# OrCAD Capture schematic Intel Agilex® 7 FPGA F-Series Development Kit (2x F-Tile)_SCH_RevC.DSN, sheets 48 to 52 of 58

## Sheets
48 PG52 VCCH_SDM: size C
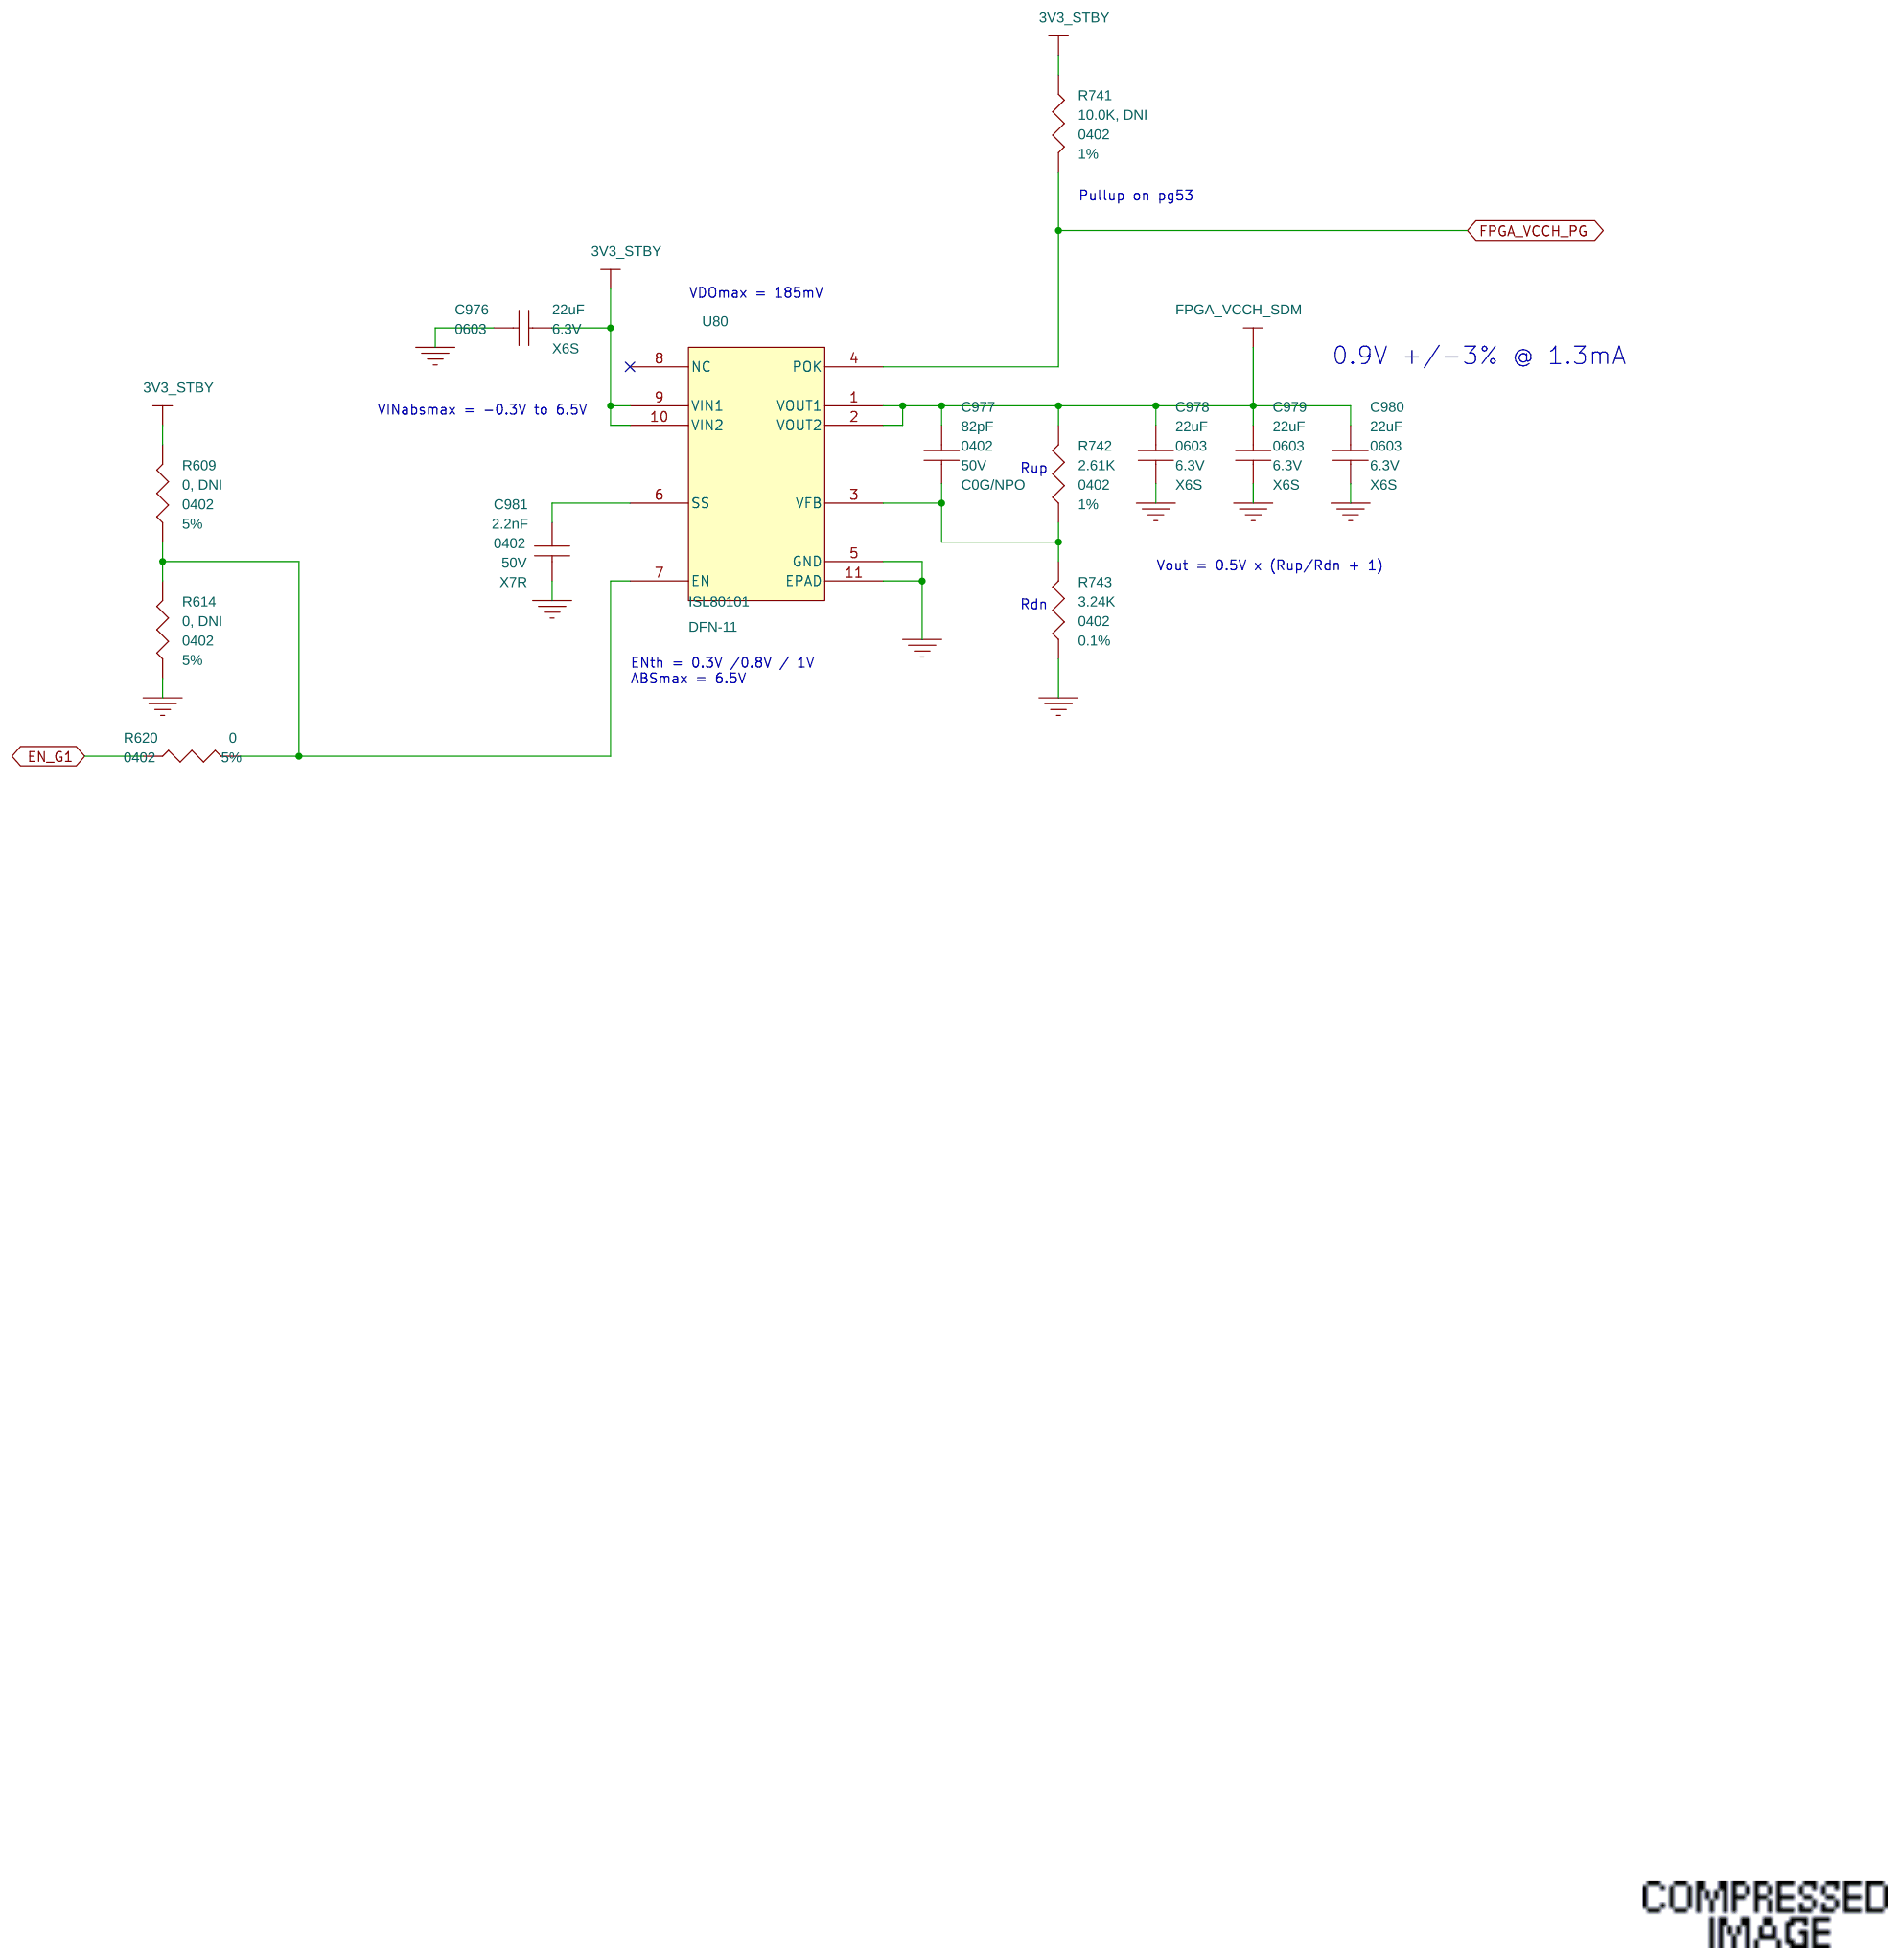
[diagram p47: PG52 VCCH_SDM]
49 PG53 VCCERT_FGT_GXF, VCCR_CORE: size C
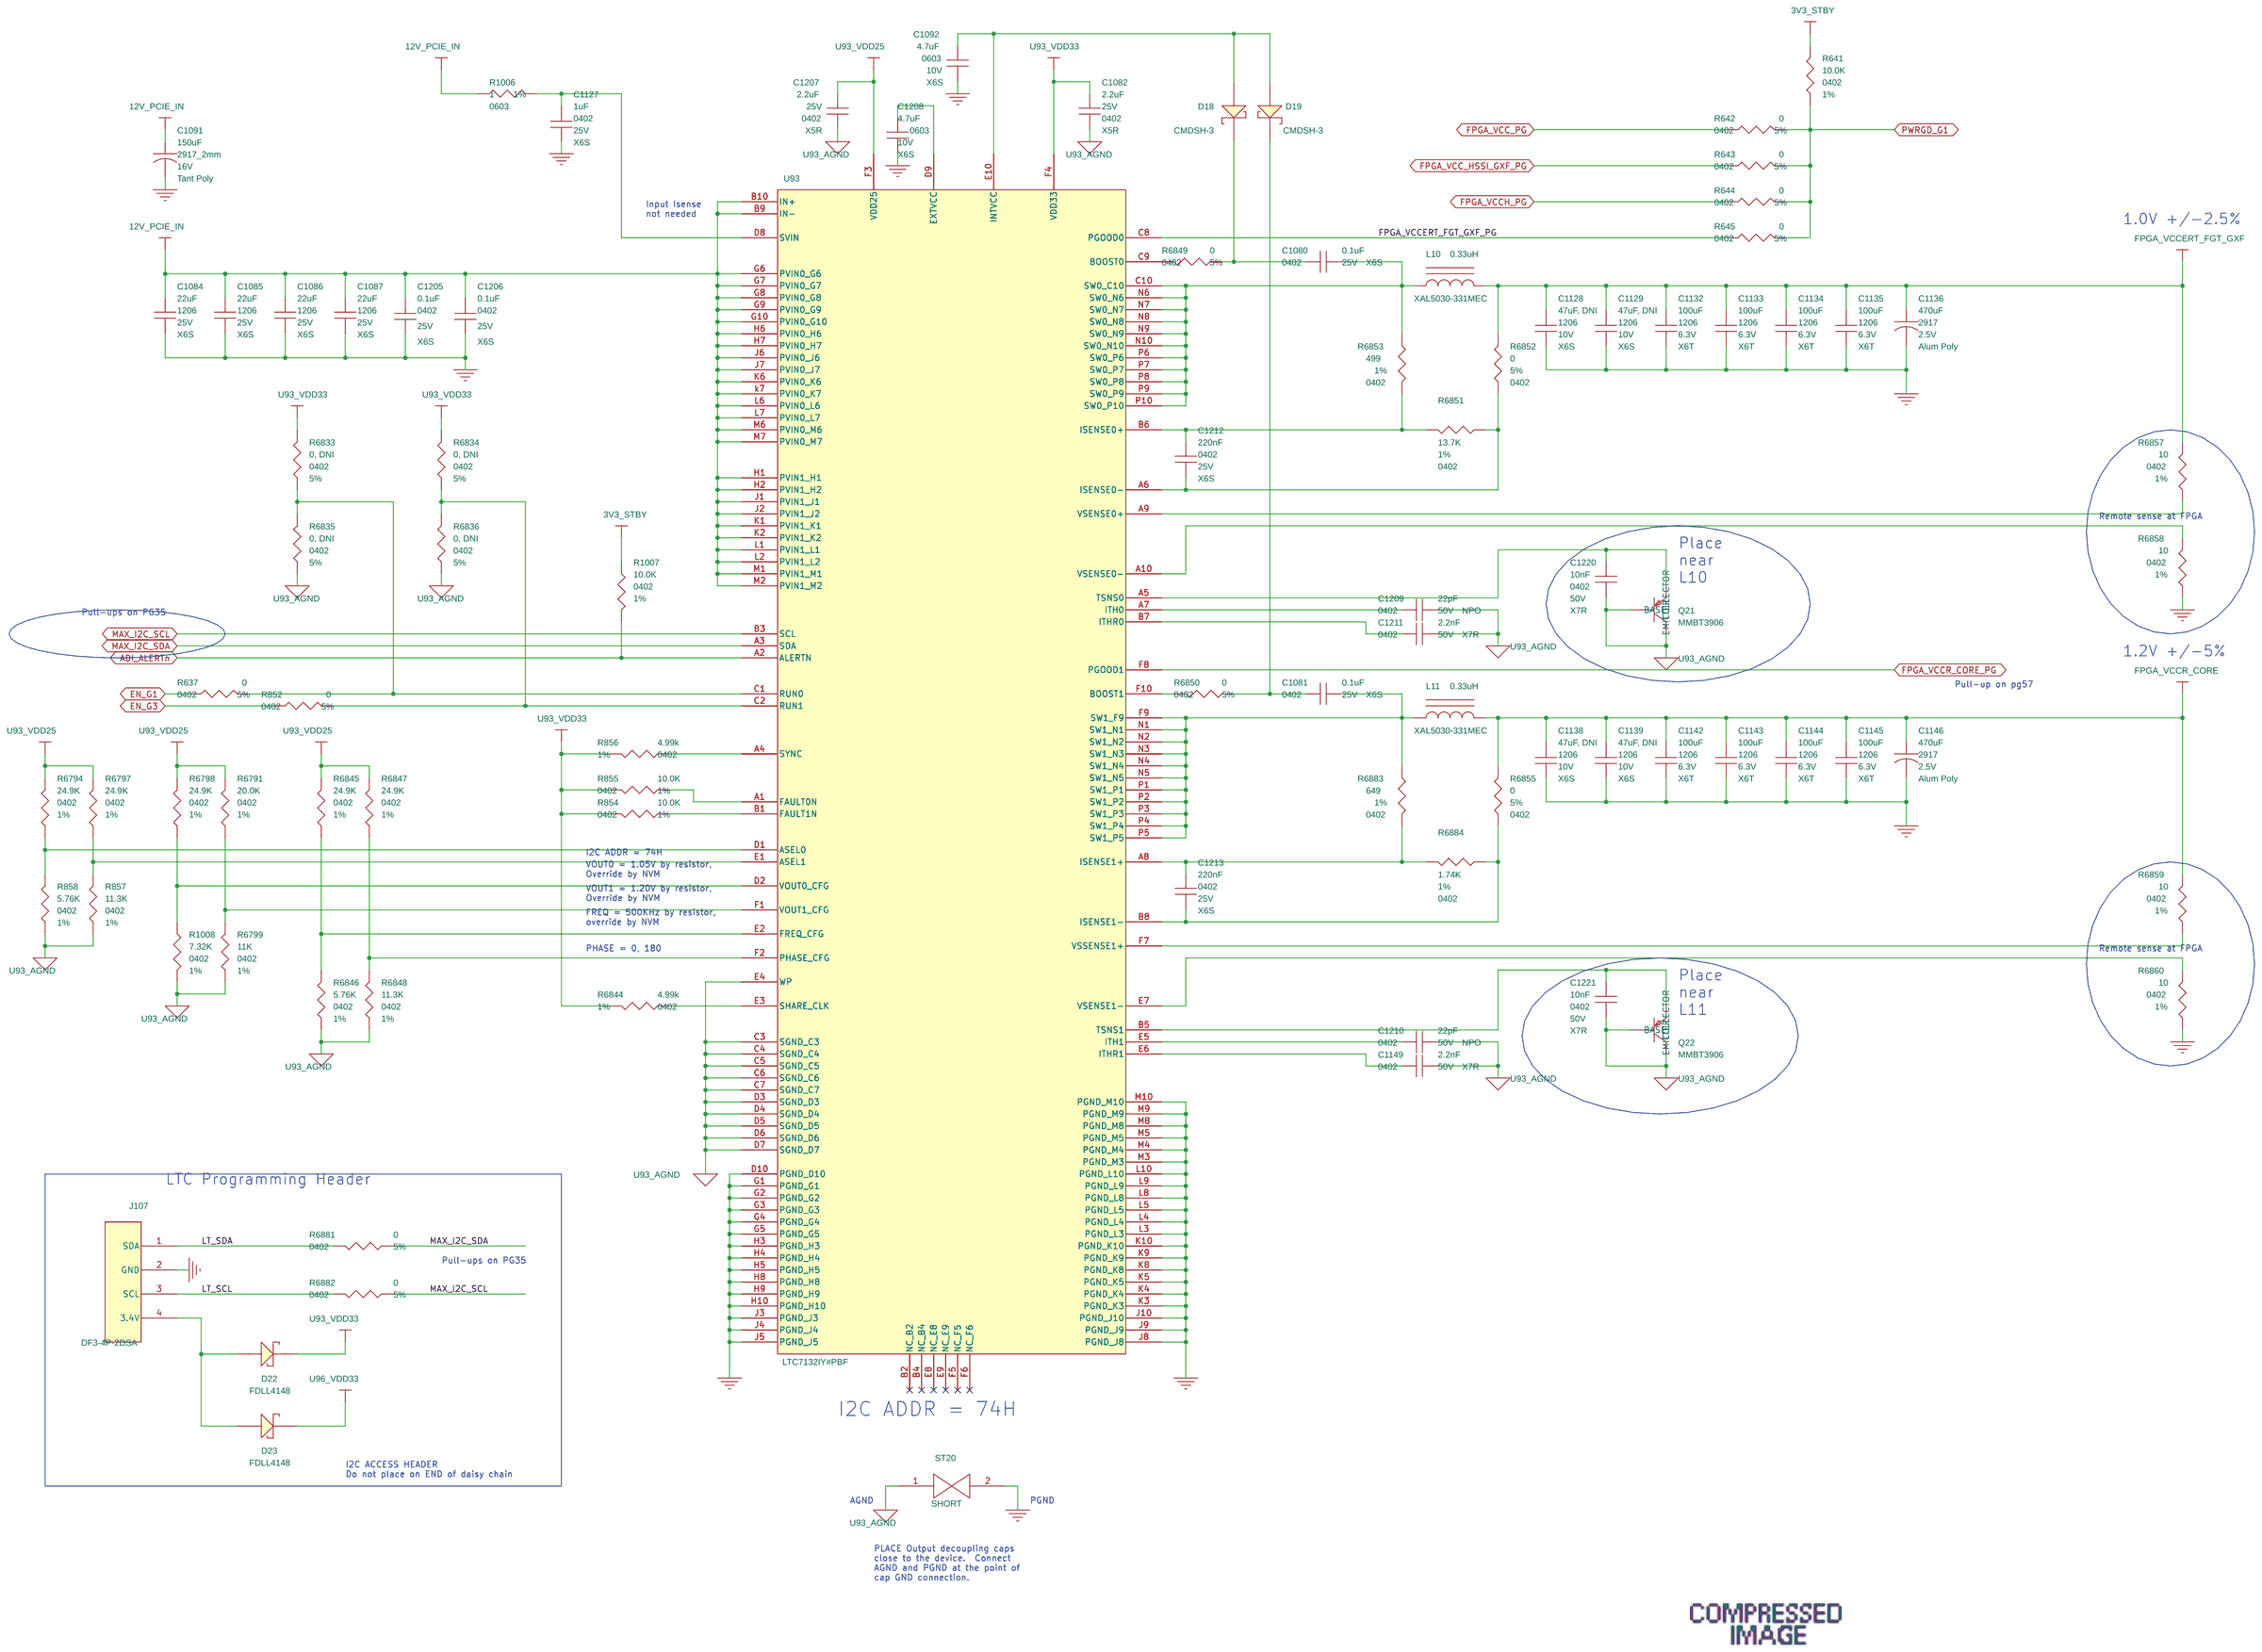
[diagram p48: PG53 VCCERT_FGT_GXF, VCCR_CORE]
50 PG54 VCCPT, VCCIO_1V2: size C
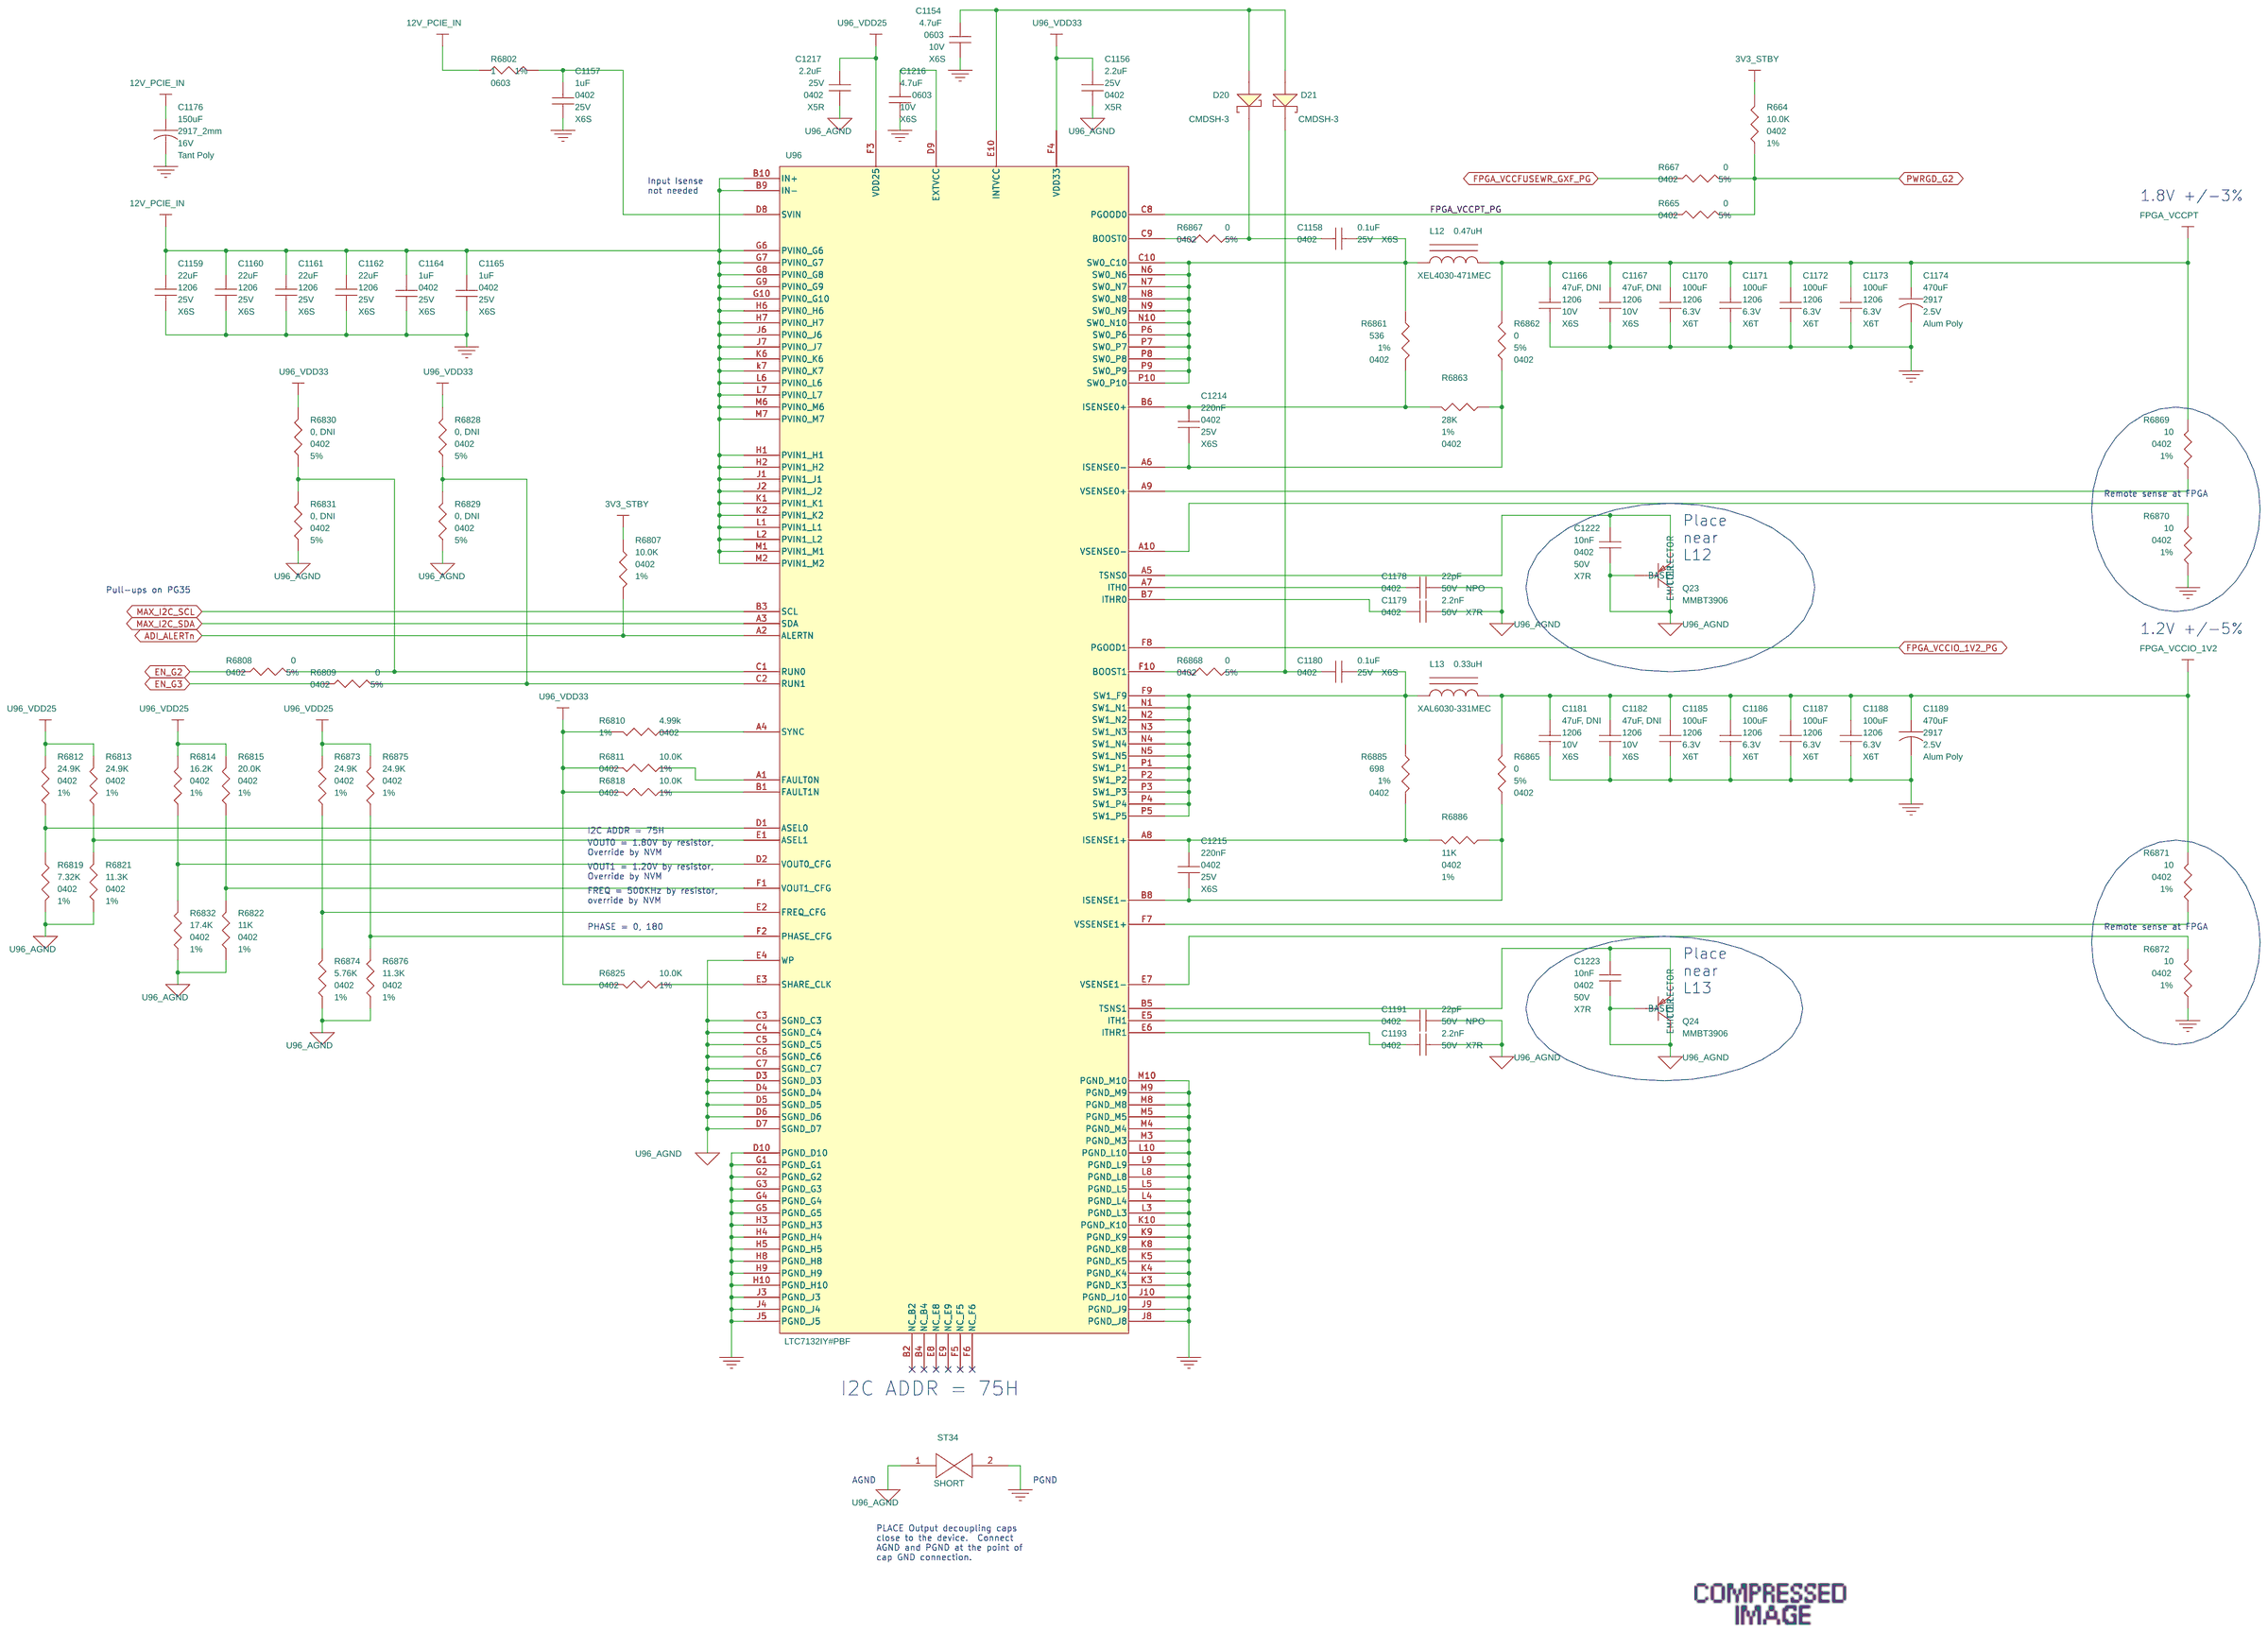
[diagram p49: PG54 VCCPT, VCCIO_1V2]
51 PG55 VCCFUSEWR_GXF: size C
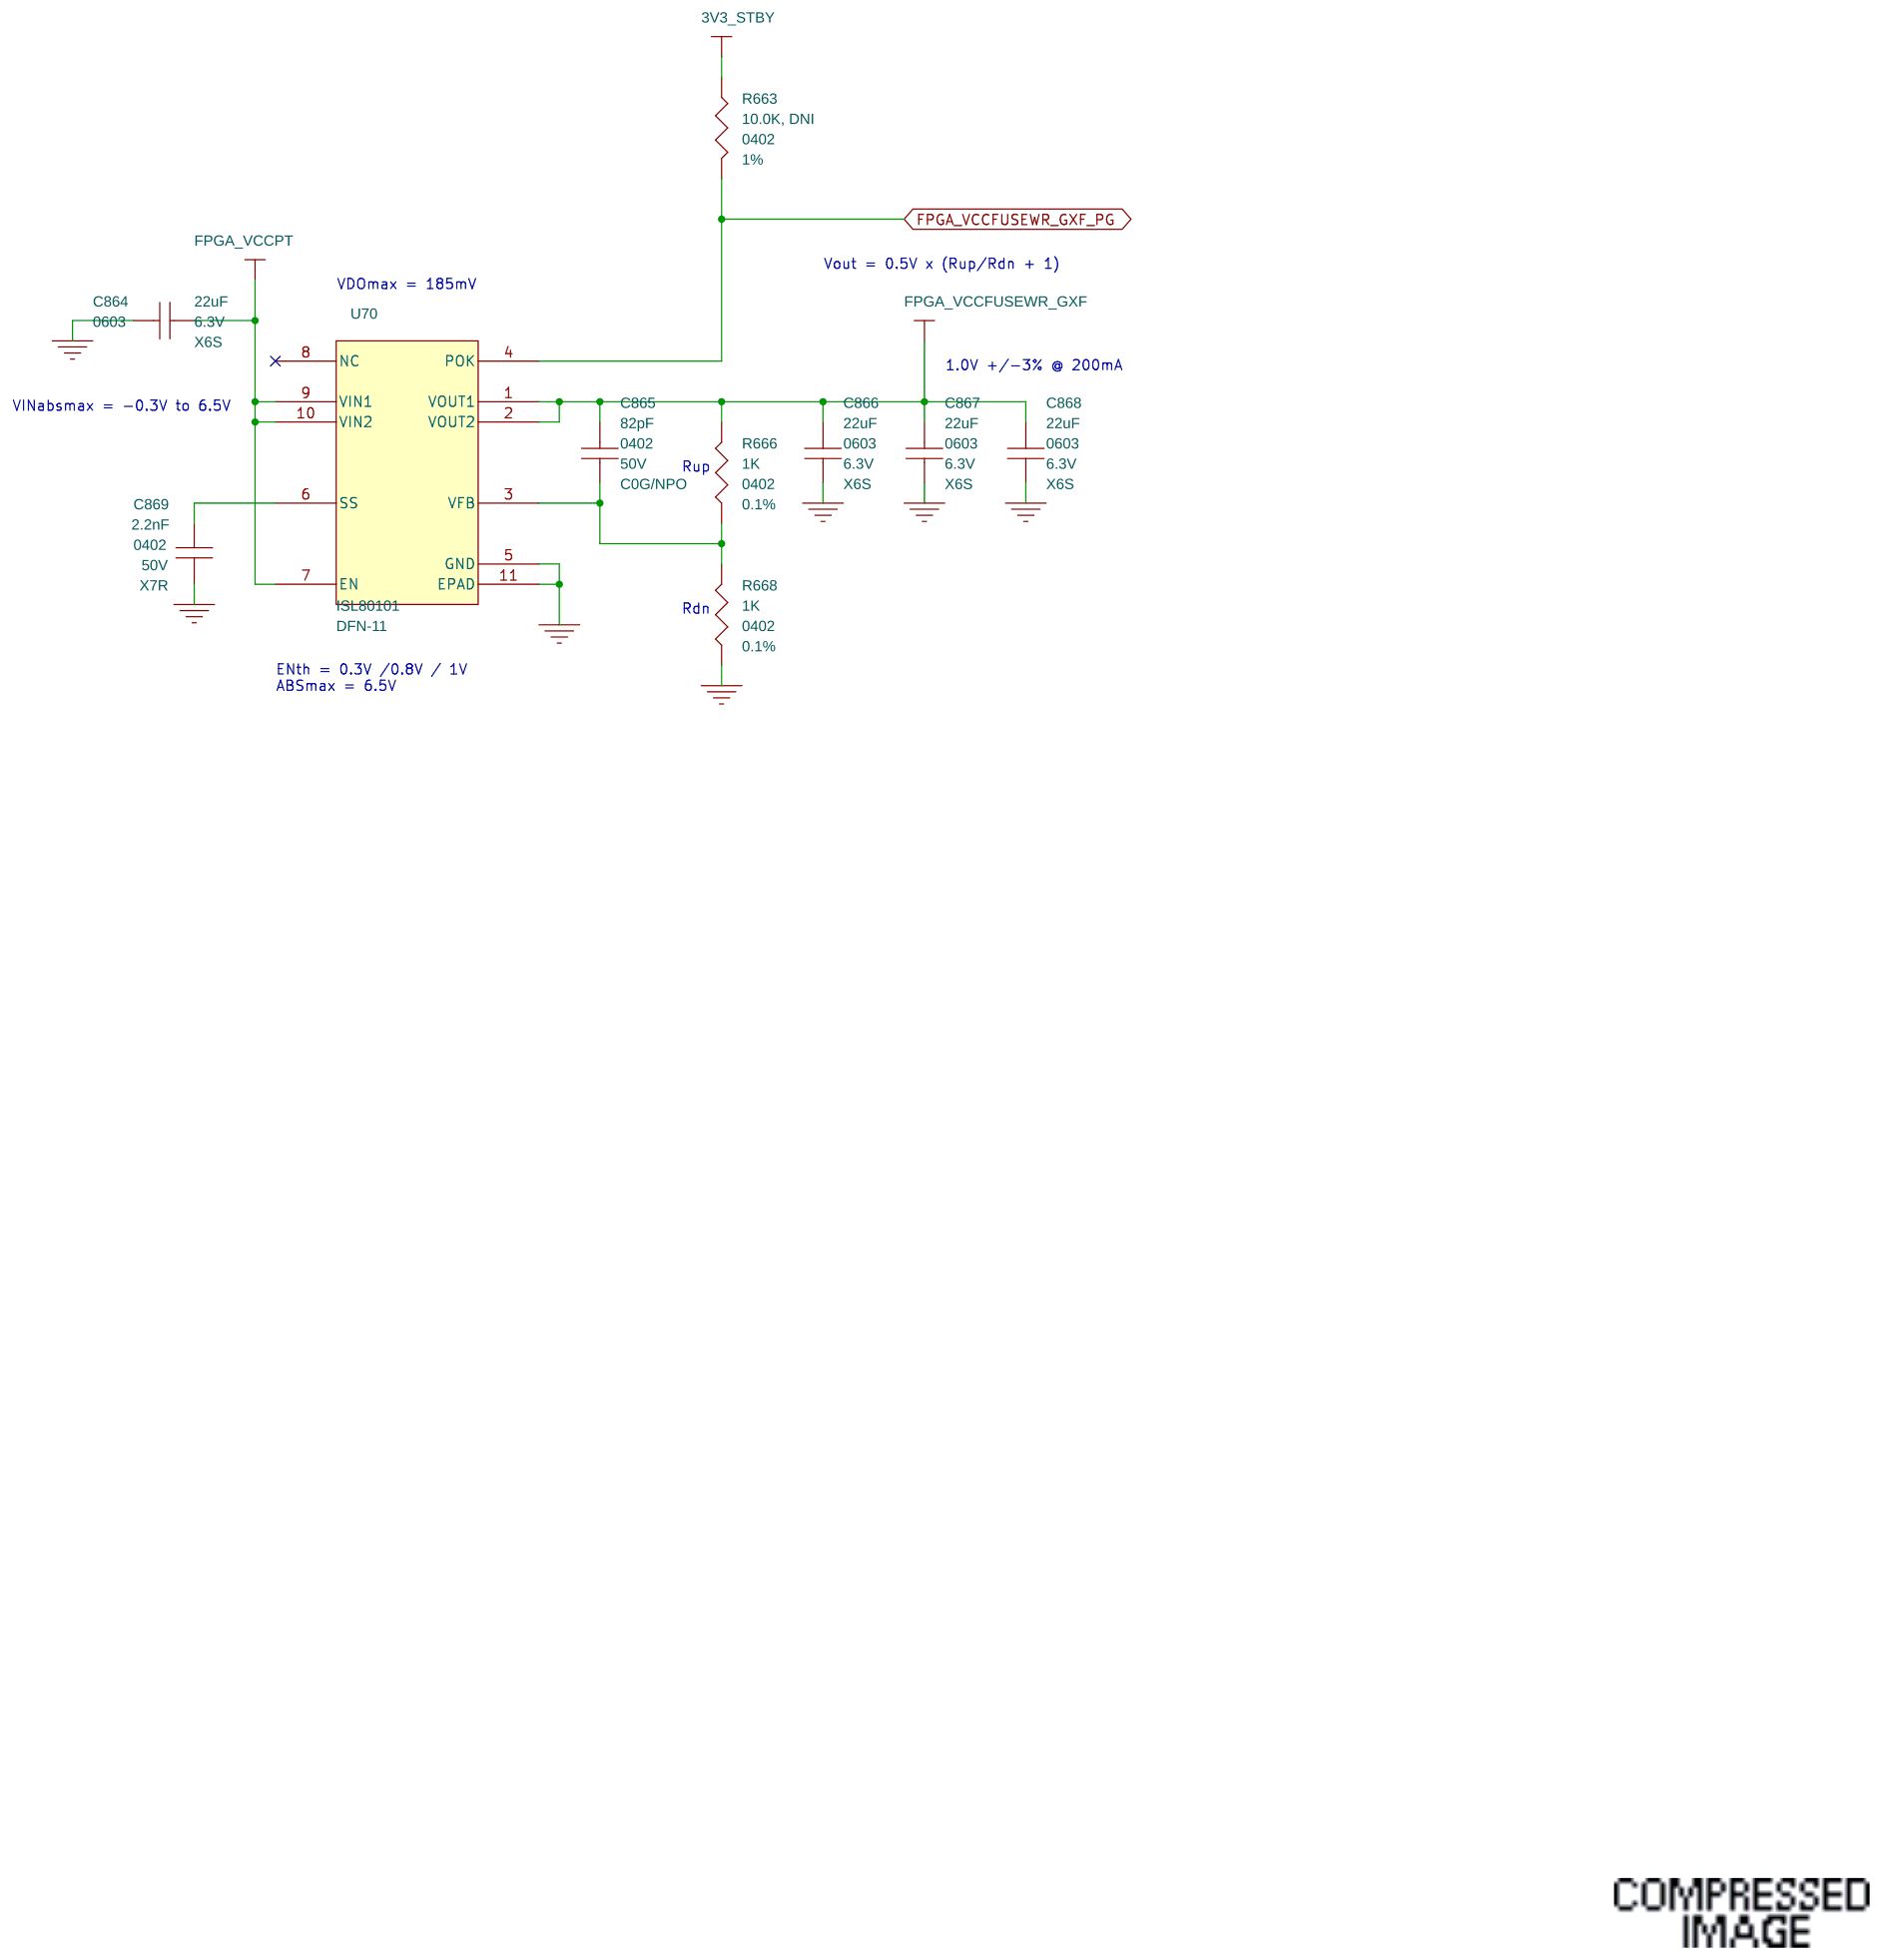
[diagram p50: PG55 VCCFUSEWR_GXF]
52 PG56 VCCBAT BATTERY: size C
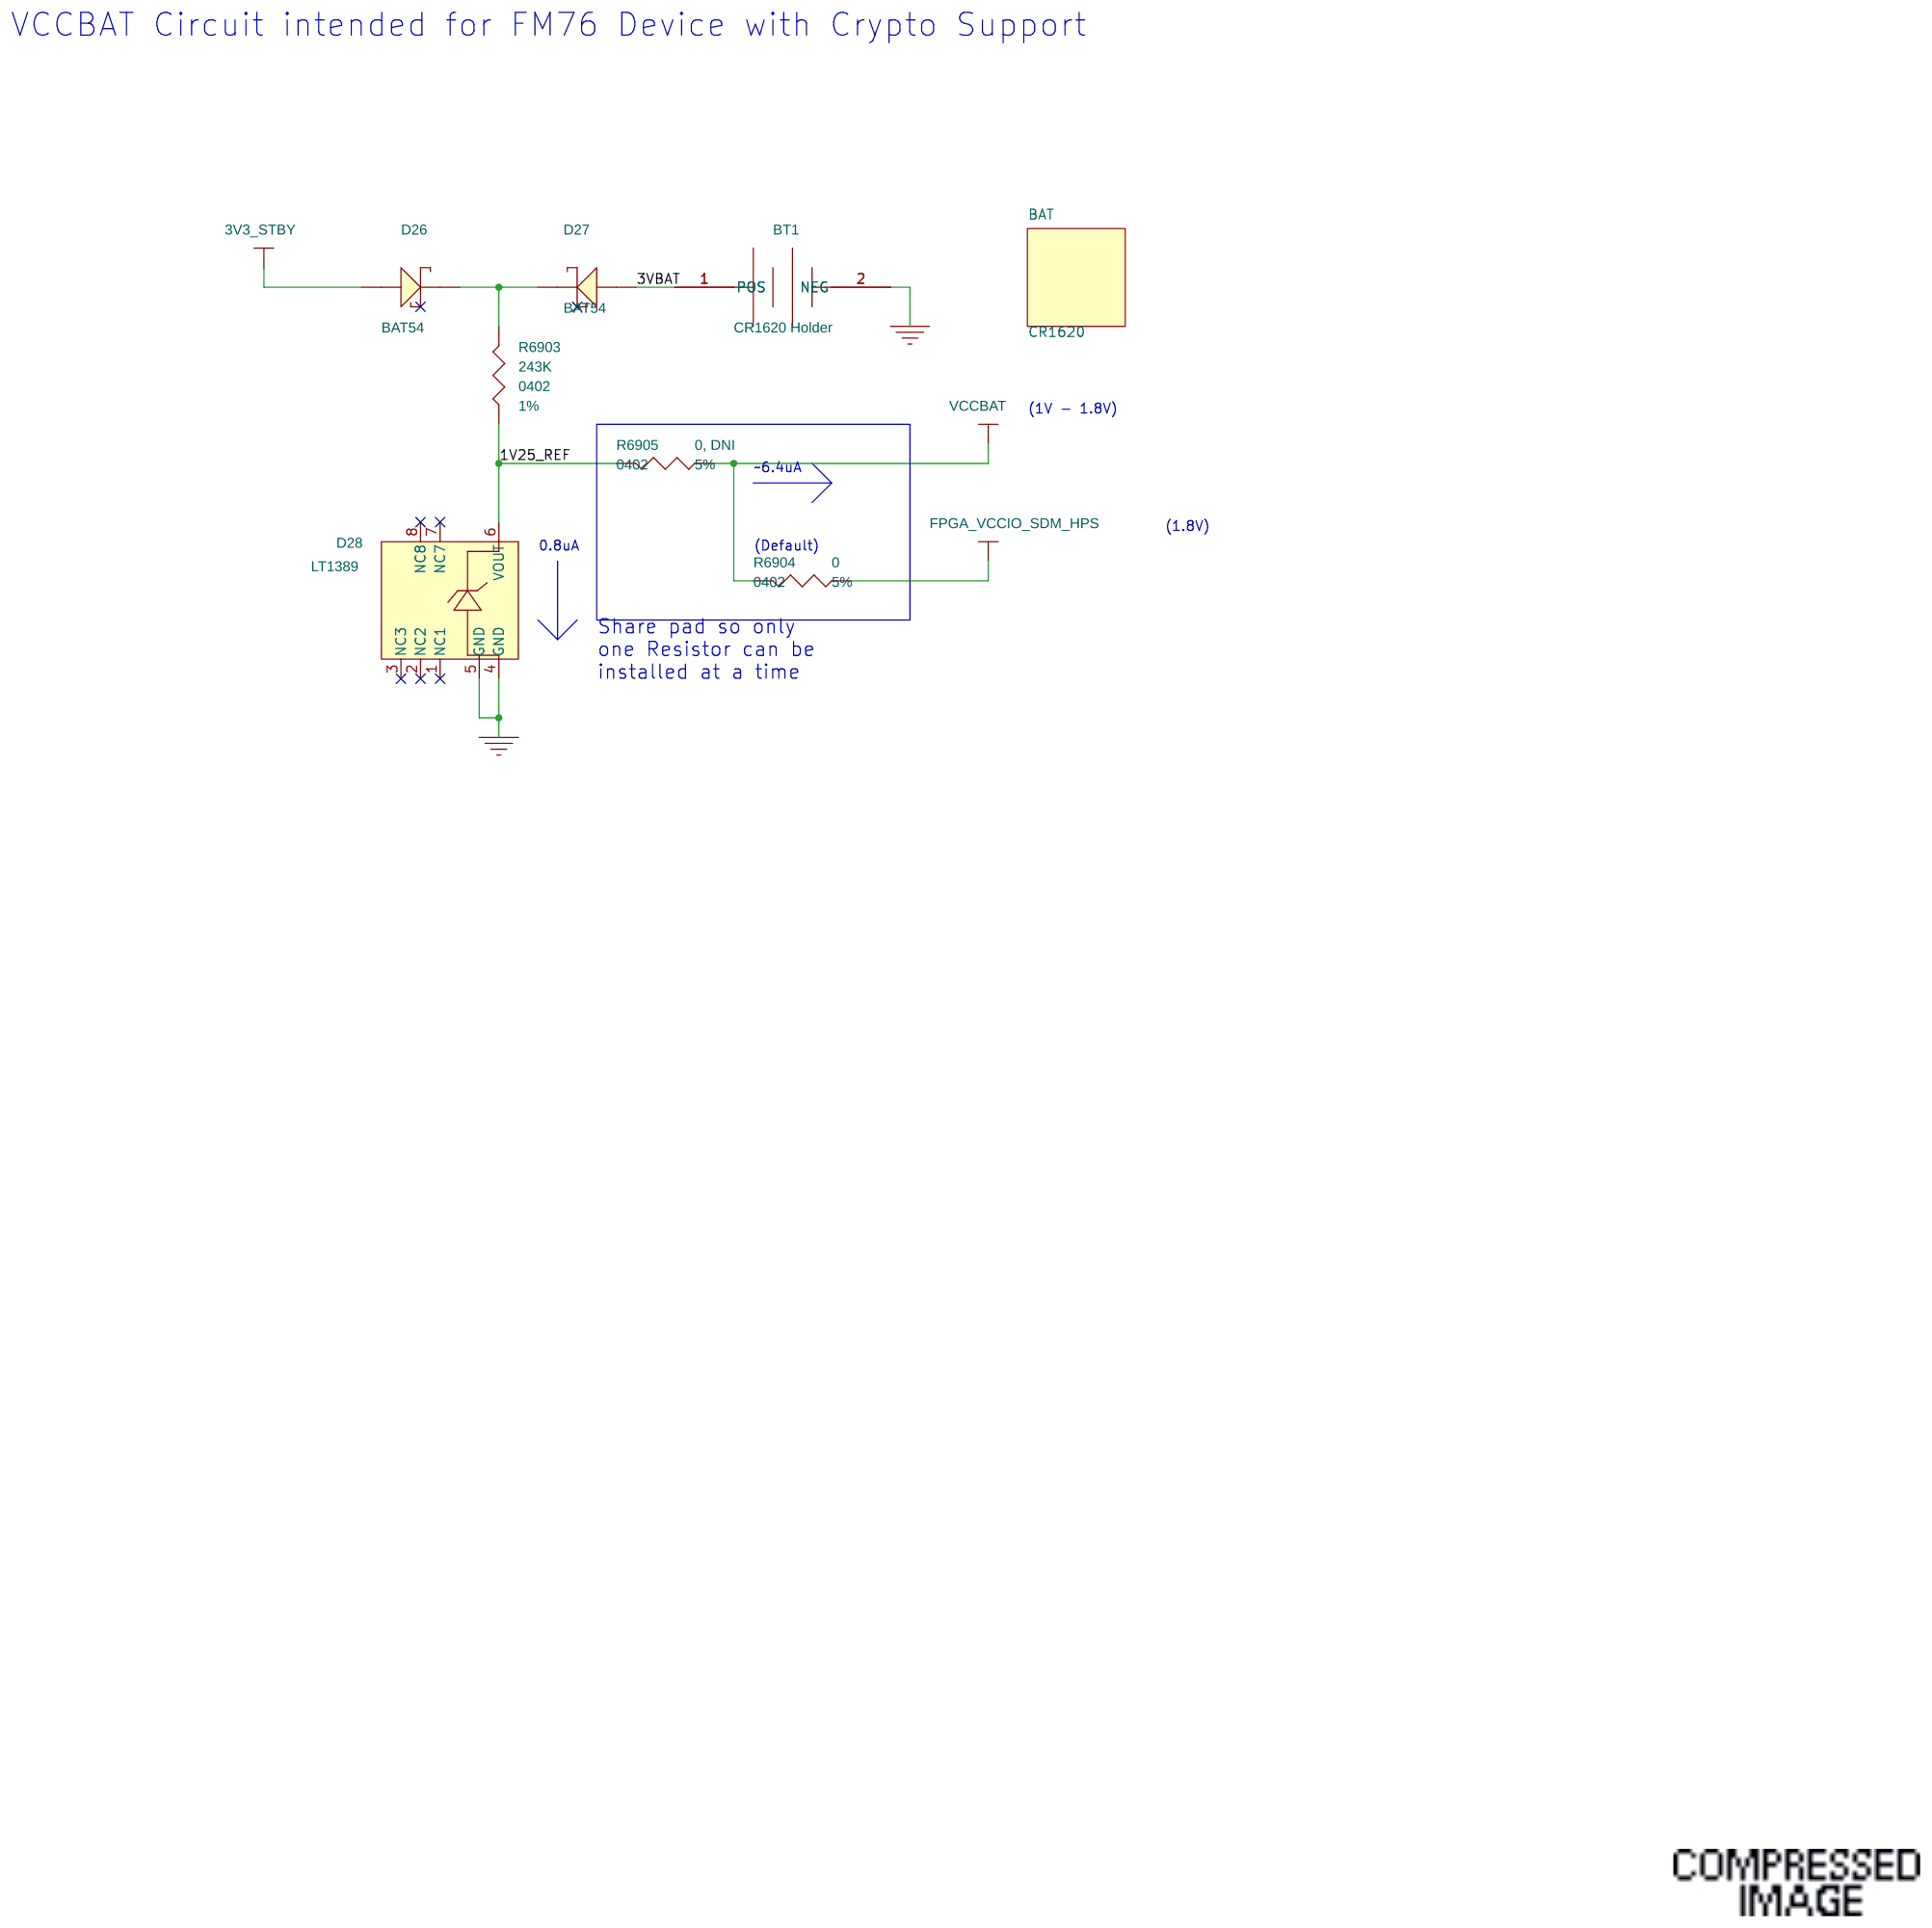
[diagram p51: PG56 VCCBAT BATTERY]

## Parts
sheet PG52 VCCH_SDM
C976  22uF  [0603]
C977  82pF  [0402]
C978  22uF  [0603]
C979  22uF  [0603]
C980  22uF  [0603]
C981  2.2nF  [0402]
R609  0, DNI  [0402]
R614  0, DNI  [0402]
R620  0  [0402]
R741  10.0K, DNI  [0402]
R742  2.61K  [0402]
R743  3.24K  [0402]
U80  ISL80101  [DFN-11]
sheet PG53 VCCERT_FGT_GXF, VCCR_CORE
C1080  0.1uF  [0402]
C1081  0.1uF  [0402]
C1082  2.2uF  [0402]
C1084  22uF  [1206]
C1085  22uF  [1206]
C1086  22uF  [1206]
C1087  22uF  [1206]
C1091  150uF  [2917_2mm]
C1092  4.7uF  [0603]
C1127  1uF  [0402]
C1128  47uF, DNI  [1206]
C1129  47uF, DNI  [1206]
C1132  100uF  [1206]
C1133  100uF  [1206]
C1134  100uF  [1206]
C1135  100uF  [1206]
C1136  470uF  [2917]
C1138  47uF, DNI  [1206]
C1139  47uF, DNI  [1206]
C1142  100uF  [1206]
C1143  100uF  [1206]
C1144  100uF  [1206]
C1145  100uF  [1206]
C1146  470uF  [2917]
C1149  2.2nF  [0402]
C1205  0.1uF  [0402]
C1206  0.1uF  [0402]
C1207  2.2uF  [0402]
C1208  4.7uF  [0603]
C1209  22pF  [0402]
C1210  22pF  [0402]
C1211  2.2nF  [0402]
C1212  220nF  [0402]
C1213  220nF  [0402]
C1220  10nF  [0402]
C1221  10nF  [0402]
D18  CMDSH-3  [SOD323]
D19  CMDSH-3  [SOD323]
D22  FDLL4148  [SOD-80]
D23  FDLL4148  [SOD-80]
J107  DF3-4P-2DSA  [DF3-4P-2DSA_01]
L10  0.33uH  [XAL5030]
L11  0.33uH  [XAL5030]
Q21  MMBT3906  [SC75_SOT416]
Q22  MMBT3906  [SC75_SOT416]
R637  0  [0402]
R641  10.0K  [0402]
R642  0  [0402]
R643  0  [0402]
R644  0  [0402]
R645  0  [0402]
R852  0  [0402]
R854  10.0K  [0402]
R855  10.0K  [0402]
R856  4.99k  [0402]
R857  11.3K  [0402]
R858  5.76K  [0402]
R1006  1  [0603]
R1007  10.0K  [0402]
R1008  7.32K  [0402]
R6791  20.0K  [0402]
R6794  24.9K  [0402]
R6797  24.9K  [0402]
R6798  24.9K  [0402]
R6799  11K  [0402]
R6833  0, DNI  [0402]
R6834  0, DNI  [0402]
R6835  0, DNI  [0402]
R6836  0, DNI  [0402]
R6844  4.99k  [0402]
R6845  24.9K  [0402]
R6846  5.76K  [0402]
R6847  24.9K  [0402]
R6848  11.3K  [0402]
R6849  0  [0402]
R6850  0  [0402]
R6851  13.7K  [0402]
R6852  0  [0402]
R6853  499  [0402]
R6855  0  [0402]
R6857  10  [0402]
R6858  10  [0402]
R6859  10  [0402]
R6860  10  [0402]
R6881  0  [0402]
R6882  0  [0402]
R6883  649  [0402]
R6884  1.74K  [0402]
ST20  SHORT  [SHORT]
U93  LTC7132IY#PBF  [BGA-140]
sheet PG54 VCCPT, VCCIO_1V2
C1154  4.7uF  [0603]
C1156  2.2uF  [0402]
C1157  1uF  [0402]
C1158  0.1uF  [0402]
C1159  22uF  [1206]
C1160  22uF  [1206]
C1161  22uF  [1206]
C1162  22uF  [1206]
C1164  1uF  [0402]
C1165  1uF  [0402]
C1166  47uF, DNI  [1206]
C1167  47uF, DNI  [1206]
C1170  100uF  [1206]
C1171  100uF  [1206]
C1172  100uF  [1206]
C1173  100uF  [1206]
C1174  470uF  [2917]
C1176  150uF  [2917_2mm]
C1178  22pF  [0402]
C1179  2.2nF  [0402]
C1180  0.1uF  [0402]
C1181  47uF, DNI  [1206]
C1182  47uF, DNI  [1206]
C1185  100uF  [1206]
C1186  100uF  [1206]
C1187  100uF  [1206]
C1188  100uF  [1206]
C1189  470uF  [2917]
C1191  22pF  [0402]
C1193  2.2nF  [0402]
C1214  220nF  [0402]
C1215  220nF  [0402]
C1216  4.7uF  [0603]
C1217  2.2uF  [0402]
C1222  10nF  [0402]
C1223  10nF  [0402]
D20  CMDSH-3  [SOD323]
D21  CMDSH-3  [SOD323]
L12  0.47uH  [XEL4030]
L13  0.33uH  [XAL6030]
Q23  MMBT3906  [SC75_SOT416]
Q24  MMBT3906  [SC75_SOT416]
R664  10.0K  [0402]
R665  0  [0402]
R667  0  [0402]
R6802  1  [0603]
R6807  10.0K  [0402]
R6808  0  [0402]
R6809  0  [0402]
R6810  4.99k  [0402]
R6811  10.0K  [0402]
R6812  24.9K  [0402]
R6813  24.9K  [0402]
R6814  16.2K  [0402]
R6815  20.0K  [0402]
R6818  10.0K  [0402]
R6819  7.32K  [0402]
R6821  11.3K  [0402]
R6822  11K  [0402]
R6825  10.0K  [0402]
R6828  0, DNI  [0402]
R6829  0, DNI  [0402]
R6830  0, DNI  [0402]
R6831  0, DNI  [0402]
R6832  17.4K  [0402]
R6861  536  [0402]
R6862  0  [0402]
R6863  28K  [0402]
R6865  0  [0402]
R6867  0  [0402]
R6868  0  [0402]
R6869  10  [0402]
R6870  10  [0402]
R6871  10  [0402]
R6872  10  [0402]
R6873  24.9K  [0402]
R6874  5.76K  [0402]
R6875  24.9K  [0402]
R6876  11.3K  [0402]
R6885  698  [0402]
R6886  11K  [0402]
ST34  SHORT  [SHORT]
U96  LTC7132IY#PBF  [BGA-140]
sheet PG55 VCCFUSEWR_GXF
C864  22uF  [0603]
C865  82pF  [0402]
C866  22uF  [0603]
C867  22uF  [0603]
C868  22uF  [0603]
C869  2.2nF  [0402]
R663  10.0K, DNI  [0402]
R666  1K  [0402]
R668  1K  [0402]
U70  ISL80101  [DFN-11]
sheet PG56 VCCBAT BATTERY
BAT  CR1620
BT1  CR1620 Holder  [16mm_Bat_Holder]
D26  BAT54  [SOT-23-3]
D27  BAT54  [SOT-23-3]
D28  LT1389  [S8]
R6903  243K  [0402]
R6904  0  [0402]
R6905  0, DNI  [0402]

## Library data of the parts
C864 C866-C868 C976 C978-C980 = CAP: CAP CER 22UF 6.3V X6S 0603; AGILE_LINK: http://sj-agile9app/Agile/PLMServlet?action=OpenEmailObject&classid=10000&objid=257560276; Item Num: H63299-001; LIFECYCLE_PHASE: Active; Lead Free Status: Not Lead Free; MFR_LIFECYCLE: Active; Manufacturer: Murata; Manufacturer Part Num: GRM188C80J226ME15D; Num Pins: 2; PART_SUBCLASS: CAPACITORS; RATED_VOLTAGE: 6.3V; RoHS Compliant: RoHS Compliant; TOLERANCE: 20%; Temperature Coefficient: X6S
C865 C977 = CAP: CAP CER 82PF 50V C0G/NPO 0402; Dielectric: C0G/NPO; Item Num: K13615-001; Lead Free Status: Yes; Manufacturer: Yageo; Manufacturer Part Num: CC0402JRNPO9BN820; Num Pins: 2; Part Class: CAPACITORS; RoHS Compliant: Yes; Temperature Coefficient: C0G/NPO; Tolerance: 5%; Voltage Rating: 50V
C869 C981 = CAP: CAP CER 2200PF 50V 10% X7R 0402; CAPACITANCE: 2200pF; Dielectric: X7R; Item Num: K13631-001; LIFECYCLE_PHASE: Active; Lead Free Status: Lead Free; Manufacturer: TDK; Manufacturer Part Num: CGJ2B2X7R1E222K050BA; Num Pins: 2; PART_SUBCLASS: CAPACITORS; Part Class: CAPACITORS; RATED_VOLTAGE: 50V; RoHS Compliant: RoHS Compliant; Temperature Coefficient: X7R; Tolerance: +/-10%
R609 R614 R6828-R6831 R6833-R6836 = RESISTOR: RES ZERO OHM 1/16W 5% 0402 SMD; IPN: A93549-001; Item Num: A93549-001; Lead Free Status: Yes; Manufacturer: Yageo; Manufacturer Part Num: RC0402JR-070RL; Num Pins: 2; Part Class: RESISTORS; RoHS Compliant: Yes; Tolerance: 5%
R620 R637 R642-R645 R665 R667 R852 R6808 R6809 R6852 R6855 R6862 R6865 = RESISTOR: RES ZERO OHM 1/16W 5% 0402 SMD; Item Num: A93549-001; Lead Free Status: Yes; Manufacturer: Yageo; Manufacturer Part Num: RC0402JR-070RL; Num Pins: 2; Part Class: RESISTORS; RoHS Compliant: Yes; Tolerance: 5%
R663 R741 = RESISTOR: RES,10.0K OHMS,1.0%,1/16W, 0402; AGILE_LINK: http://sj-agile9app/Agile/PLMServlet?action=OpenEmailObject&classid=10000&objid=146548997; Item Num: K28115-001; LIFECYCLE_PHASE: Active; Lead Free Status: Yes; MFR_LIFECYCLE: Active; Manufacturer: Panasonic; Manufacturer Part Num: ERJ-2RKF1002X; Num Pins: 2; PART_SUBCLASS: RESISTORS; POWER: 1/16W; RESISTANCE: 10.0K; RoHS Compliant: Yes; TOLERANCE: 1%
R742 = RESISTOR: RES SMD 2.61K 1% 1/16W 0402; Item Num: A93548-419; Lead Free Status: Yes; Manufacturer: RC0402FR-072K61L; Manufaturer: Yageo; Num Pins: 2; Part Class: RESISTORS; RoHS Compliant: Yes; TOLERANCE: 1%
R743 = RESISTOR: RES SMD 3.24KOHM 0.1% 1/16W 0402; Item Num: C79651-108; Lead Free Status: Yes; Manufacturer: Yageo; Manufacturer Part Num: RE0402BRE073K24L; Num Pins: 2; Part Class: Resistors; Power Rating: 1/16W; RoHS Compliant: Yes; TOLERANCE: 0.1%
U70 U80 = EY1501di-adj: IC, Linear Regulator, 1A; Item Num: E81353-001; Manufacturer: Intel/Enpirion; Manufacturer Part Num: EY1501DI-ADJ
C1080 C1081 C1158 C1180 C1205 C1206 = CAP: CAP CER 0.1UF 25V X6S 0402; Dielectric: X6S; IPN: K19434-001; Item Num: K19434-001; LIFECYCLE_PHASE: Active; Lead Free Status: Lead Free; MFR_LIFECYCLE: Active; Manufacturer: Murata; Manufacturer Part Num: GRM155C81E104KA12D; Num Pins: 2; PART_SUBCLASS: CAPACITORS; Part Class: CAPACITORS; RATED_VOLTAGE: 25V; RoHS Compliant: RoHS Compliant; Temperature Coefficient: X6S; Tolerance: 10%
C1082 C1156 C1207 C1217 = CAP: CAPC,X5R,0402,2.2UF,25.00V,+/- 10%; CLASS: DISCRETE; Dielectric Type: X5R; FPLIST: CC0805N,CC0805L,CC0805M; IPN: H87713-001; Item Num: H87713-001; Manufacturer: Murata; Manufacturer PN: GRM155R61E225KE11D; Manufacturer Part Num: GRM155R61E225KE11D; PART_NUMBER: 150-0578; Rated Voltage: 25V; Temperature Coefficient: X5R; Tolerance: 10%
C1084-C1087 C1159-C1162 = CAP: CAP CER 22UF 25V X6S 1206; AGILE_LINK: http://sj-agile9app/Agile/PLMServlet?action=OpenEmailObject&classid=10000&objid=257560276; Item Num: H65936-001; LIFECYCLE_PHASE: Active; Lead Free Status: Lead Free; MFR_LIFECYCLE: Active; Manufacturer: Murata; Manufacturer Part Num: GRM31CC81E226KE11L; Num Pins: 2; PART_SUBCLASS: CAPACITORS; RATED_VOLTAGE: 25V; RoHS Compliant: RoHS Compliant; TOLERANCE: 10%; Thermal Coefficient: X6S
C1091 C1176 = PCAP: CAP TANT POLY 150UF 16V 2917; AGILE_LINK: http://sj-agile9app/Agile/PLMServlet?action=OpenEmailObject&classid=10000&objid=257237054; CAPACITANCE: 100uF; Item Num: H97831-001; LIFECYCLE_PHASE: Active; Lead Free Status: Lead Free; MFR_LIFECYCLE: Active; Manufacturer: Panasonic; Manufacturer Part Num: 1CTQC15173F1; Num Pins: 2; PART_SUBCLASS: CAPACITORS; RATED_VOLTAGE: 16V; RoHS Compliant: RoHS Compliant; TOLERANCE: 20%; Type: Tant Poly
C1092 C1154 C1208 C1216 = CAP: CAP CER 4.7UF 10V X6S 0603; AGILE_LINK: http://sj-agile9app/Agile/PLMServlet?action=OpenEmailObject&classid=10000&objid=242850622; Item Num: K19437-001; LIFECYCLE_PHASE: Active; MFR_LIFECYCLE: Active; Manufacturer: Murata; Manufacturer Part Num: GRM185C81A475KE11D; Num Pins: 2; PACKAGING: Tape & Reel (TR); PART_SUBCLASS: CAPACITORS; RATED_VOLTAGE: 10V; RoHS Compliant: RoHS Compliant; TOLERANCE: 10%; Temperature Coefficient: X6S
C1127 C1157 C1164 C1165 = CAP: CAP CER 1UF 25V X6S 0402; Item Num: H81594-001; Lead Free Status: Yes; Manufacturer: Murata; Manufacturer Part Num: GRM155C81E105KE11D; Num Pins: 2; Part Class: CAPACITORS; RATED_VOLTAGE: 25V; RoHS Compliant: Yes; Temperature Coefficient: X6S
C1128 C1129 C1138 C1139 C1166 C1167 C1181 C1182 = CAP: CAP CER 47UF 10V X6S 1206; AGILE_LINK: http://sj-agile9app/Agile/PLMServlet?action=OpenEmailObject&classid=10000&objid=257560276; CAPACITANCE: 47uF; Item Num: H65935-001; LIFECYCLE_PHASE: Active; Lead Free Status: Not Lead Free; MFR_LIFECYCLE: Active; Manufacturer: TDK; Manufacturer Part Num: C3216X6S1A476M160AC; Num Pins: 2; PART_SUBCLASS: CAPACITORS; RATED_VOLTAGE: 10V; RoHS Compliant: RoHS Compliant; TOLERANCE: 20%; TYPE: X6S
C1132-C1135 C1142-C1145 C1170-C1173 C1185-C1188 = CAP: CAP CER 100UF 6.3V X6T 1206; Dielectric Type: X6T; Item Num: H65271-004; LIFECYCLE_PHASE: Active; Lead Free Status: Lead Free; MFR_LIFECYCLE: Active; Manufacturer: Murata; Manufacturer PN: GRM31CD80J107ME39L; Manufacturer Part Num: GRM31CD80J107ME39L; Num Pins: 2; PART_SUBCLASS: CAPACITORS; RATED_VOLTAGE: 6.3V; Rated Voltage: 6.3V; RoHS Compliant: RoHS Compliant; TOLERANCE: 20%; Temperature Coefficient: X6T; Working Voltage: 6.3V
C1136 C1146 C1174 C1189 = PCAP: Cap Aluminum 470uF 2.5V 20% 2917 Flat 0.003 Ohm 10200mA 2000hr 105°C; AGILE_LINK: http://sj-agile9app/Agile/PLMServlet?action=OpenEmailObject&classid=10000&objid=257237054; Item Num: K22160-001; LIFECYCLE_PHASE: Active; Lead Free Status: Lead Free; MFR_LIFECYCLE: Active; Manufacturer: Panasonic; Manufacturer Part Num: EEF-GX0E471R; Num Pins: 2; PART_SUBCLASS: CAPACITORS; RATED_VOLTAGE: 2.5V; RoHS Compliant: RoHS Compliant; TOLERANCE: 20%; Type: Alum Poly
C1149 C1179 C1193 C1211 = CAP: CAP CER 2200PF 50V 10% X7R 0402; CAPACITANCE: 2200pF; Dielectric: X7R; Item Num: K13631-001; LIFECYCLE_PHASE: Active; Lead Free Status: Lead Free; Manufacturer: TDK; Manufacturer Part Num: CGJ2B2X7R1E222K050BA; Num Pins: 2; PART_SUBCLASS: CAPACITORS; Part Class: CAPACITORS; RATED_VOLTAGE: 50V; RoHS Compliant: RoHS Compliant; TOLERANCE: +/-10%; Temperature Coefficient: X7R
C1178 C1191 C1209 C1210 = CAP: CAP - CER, 22PF, 50V, +/-5%, NP0, 0402 SMD; AGILE_LINK: http://sj-agile9app/Agile/PLMServlet?action=OpenEmailObject&classid=10000&objid=213459014; Dielectric: NPO; Item Num: K21350-001; Lead Free Status: Lead Free; MFR_LIFECYCLE: Active; Manufacturer: Yageo; Manufacturer Part Num: CC0402JRNPO9BN220; Num Pins: 2; PART_SUBCLASS: CAPACITORS; RATED_VOLTAGE: 50V; RoHS Compliant: Yes; Voltage: 50V
C1212-C1215 = CAP: CAP CER 0.22UF 25V X6S 0402; CAPACITANCE: 0.1uF; Dielectric: X6S; Item Num: K19428-001; LIFECYCLE_PHASE: Active; Lead Free Status: Lead Free; Manufacturer: Murata; Manufacturer Part Num: GRT155C81E224KE01D; Num Pins: 2; Part Class: CAPACITORS; RATED_VOLTAGE: 25V; RoHS Compliant: RoHS Compliant; Tolerance: 10%
C1220-C1223 = Cap_10000PF_50V_0402: CAP - CER, 10NF, 50V, +/-10%, X7R, 0402 SMD; Dielectric: X7R; Item Num: H61346-001; LIFECYCLE_PHASE: Active; Lead Free Status: Lead Free; Manufacturer Part Num: GRM155R71H103KA88D; Num Pins: 2; Part Class: CAPACITORS; RATED_VOLTAGE: 50V; RoHS Compliant: RoHS Compliant; Temperature Coefficient: X7R; Tolerance: 10%; Voltage: 50V
D18-D21 = TVS_5p0SMDJ12A: DIODE 30V SCHOTTKY SMD; Item Num: M59439-001; Manufacturer: Central Semiconductor; Manufacturer Part Num: CMDSH-3 TR PBFREE
D22 D23 = TVS_5p0SMDJ12A: DIODE GEN PURP 100V 200MA SOD80; Item Num: 200947-901; Manufacturer: Fairchild
J107 = DF3-4P-2DSA: CONN_HDR,4X1,PLG,VT,2.0000mm,9ST,BK; Item Num: M53332-001; Manufacturer: Hirose Electric; Manufacturer Part Num: DF3-4P-2DSA(01)
L10 L11 = INDUCTOR_IRON_ALT: IND 330nH SHLD 20% 25A 2.53mOHM; CLASS: DISCRETE; Item Num: H49150-001; Manufacturer: Coilcraft; Manufacturer Part Num: XAL5030-331MEC
Q21-Q24 = 2N3906_0: TRANS PNP 40V 200MA SC75 SOT416; Item Num: K13941-001; Manufacturer: On-Semi; Manufacturer Part Num: MMBT3906TT1G
R641 R664 R854 R855 R1007 R6807 R6811 R6818 R6825 = RESISTOR: RES,10.0K OHMS,1.0%,1/16W, 0402; AGILE_LINK: http://sj-agile9app/Agile/PLMServlet?action=OpenEmailObject&classid=10000&objid=146548997; Item Num: K28115-001; LIFECYCLE_PHASE: Active; Lead Free Status: Yes; MFR_LIFECYCLE: Active; Manufacturer: Panasonic; Manufacturer Part Num: ERJ-2RKF1002X; Num Pins: 2; PART_SUBCLASS: RESISTORS; POWER: 1/16W; RoHS Compliant: Yes; TOLERANCE: 1%
R856 R6810 R6844 = RES: RES D,0402,4.99 kOHM,1.00%,1/16W; CLASS: DISCRETE; Item Num: A93548-202; Manufacturer: Vishay; Manufacturer PN: CRCW04024K99FKED; Manufacturer Part Num: CRCW04024K99FKED; Rated Power: 1/10W; Tolerance: 1%
R857 R6821 R6848 R6876 = RESISTOR: RES 11.3K OHM 1% 1/16W 0402; AGILE_LINK: http://sj-agile9app/Agile/PLMServlet?action=OpenEmailObject&classid=10000&objid=146548997; Item Num: K32789-001; LIFECYCLE_PHASE: Active; Lead Free Status: Yes; MFR_LIFECYCLE: Active; Manufacturer: Yageo; Manufacturer Part Num: RC0402FR-0711K3L; Num Pins: 2; PART_SUBCLASS: RESISTORS; POWER: 1/16W; RoHS Compliant: Yes; TOLERANCE: 1%
R858 R6846 R6874 = RESISTOR: RES SMD 5.76K OHM 1% 1/10W 0402; AGILE_LINK: http://sj-agile9app/Agile/PLMServlet?action=OpenEmailObject&classid=10000&objid=146548997; Item Num: K15735-001; LIFECYCLE_PHASE: Active; Lead Free Status: No; MFR_LIFECYCLE: Active; Manufacturer: Panasonic; Manufacturer Part Num: ERJ-2RKF5761X; Num Pins: 2; PART_SUBCLASS: RESISTORS; POWER: 1/10W; RoHS Compliant: Yes; TOLERANCE: 1%
R1006 R6802 = RES: RES.,1 OHM,1%,1/10W,0603; CLASS: DISCRETE; FPLIST: CR0603N,CR0603L,CR0603M; IPN: xxxxxx-xxx; Item Num: A93550-324; Manufacturer: YAGEO; Manufacturer PN: RC0603FR-071RL; Manufacturer Part Num: RC0603FR-071RL; PART_NUMBER: 100-0163; Rated Power: 1/10W; Temperature Coefficient: 200ppm/C; Tolerance: 1%
R1008 R6819 = RESISTOR: RES 7.32K OHM 1% 1/16W 0402; Item Num: A93548-425; Lead Free Status: Yes; Manufacturer: Yageo; Manufacturer Part Num: RC0402FR-077K32L; Num Pins: 2; Part Class: Resistors; TOLERANCE: 1%
R6791 R6815 = RESISTOR: RES 20.0K ohm, 1/16W 1% 0402; AGILE_LINK: http://sj-agile9app/Agile/PLMServlet?action=OpenEmailObject&classid=10000&objid=146548997; Item Num: A93548-181; LIFECYCLE_PHASE: Active; Lead Free Status: No; MFR_LIFECYCLE: Active; Manufacturer: Yageo; Manufacturer Part Num: RC0402FR-0720KL; Num Pins: 2; PART_SUBCLASS: RESISTORS; POWER: 1/16W; RoHS Compliant: Yes; TOLERANCE: 1%
R6794 R6797 R6798 R6812 R6813 R6845 R6847 R6873 R6875 = RESISTOR: RES 24.9K OHM 1% 1/16W 0402; AGILE_LINK: http://sj-agile9app/Agile/PLMServlet?action=OpenEmailObject&classid=10000&objid=146548997; Item Num: K68934-001; LIFECYCLE_PHASE: Active; Lead Free Status: Yes; MFR_LIFECYCLE: Active; Manufacturer: Yageo; Manufacturer Part Num: RC0402FR-0724K9L; Num Pins: 2; PART_SUBCLASS: RESISTORS; POWER: 1/16W; RoHS Compliant: Yes; TOLERANCE: 1%
R6799 R6822 R6886 = RESISTOR: RES 11K OHM 1% 1/16W 0402; AGILE_LINK: http://sj-agile9app/Agile/PLMServlet?action=OpenEmailObject&classid=10000&objid=146548997; Item Num: A93548-227; LIFECYCLE_PHASE: Active; Lead Free Status: Yes; MFR_LIFECYCLE: Active; Manufacturer: Yageo; Manufacturer Part Num: RC0402FR-0711KL; Num Pins: 2; PART_SUBCLASS: RESISTORS; POWER: 1/16W; RoHS Compliant: Yes; TOLERANCE: 1%
R6849 R6850 R6867 R6868 R6881 R6882 R6904 = RESISTOR: RES ZERO OHM 1/16W 5% 0402 SMD; Item Num: A93549-001; Lead Free Status: No; Manufacturer: Yageo; Manufacturer Part Num: RC0402JR-070RL; Num Pins: 2; Part Class: RESISTORS; RoHS Compliant: Yes; Tolerance: 5%
R6851 = RESISTOR: RES 13.7K OHM 1/16W 1% 0402 SMD; Item Num: A93548-377; Lead Free Status: Yes; Manufacturer: Yageo; Manufacturer Part Num: RC0402FR-0713K7L; Num Pins: 2; Part Class: RESISTORS; Price: 0; RoHS Compliant: Yes; Tolerance: 1%
R6853 = RESISTOR: RES 499 OHM 1/16W 1% 0402 SMD; Item Num: A93548-094; Lead Free Status: Yes; Manufacturer: Yageo; Manufacturer Part Num: RC0402FR-07499RL; Num Pins: 2; Part Class: RESISTORS; RoHS Compliant: Yes; Tolerance: 1%
R6857-R6860 R6869-R6872 = RESISTOR: RES, 10 OHM, 1%, 1/16W, 0402; Item Num: A80345-001; LIFECYCLE_PHASE: Active; Lead Free Status: Yes; Manufacturer: Panasonic; Manufacturer Part Num: ERJ-2RKF10R0X; Num Pins: 2; PART_SUBCLASS: RESISTORS; POWER: 1/16W; Part Class: Resistors; RoHS Compliant: Yes; TOLERANCE: 1%
R6883 = RESISTOR: RES 649 OHM 1/16W 1% 0402 SMD; Item Num: A93548-011; Lead Free Status: Yes; Manufacturer: Vishay Dale; Manufacturer Part Num: CRCW0402649RFKED; Num Pins: 2; Part Class: RESISTORS; Price: 0; RoHS Compliant: Yes; Tolerance: 1%
R6884 = RESISTOR: RES 1.74K OHM 1/16W 1% 0402 SMD; Item Num: A93548-118; Lead Free Status: Yes; Manufacturer: Yageo; Manufacturer Part Num: RC0402FR-071K74L; Num Pins: 2; Part Class: RESISTORS; Price: 0; RoHS Compliant: Yes; Tolerance: 1%
ST20 ST34 = SHORT
U93 U96 = LTC7132IY#PBF: IC, LIN, BGA, LTC7132, DC/DC Regulator; Item Num: M59347-001; Manufacturer: ADI
L12 = INDUCTOR_IRON_ALT: IND, 0.47uH, 15.5A, 4.1mOHM, CUBE, SM; CLASS: DISCRETE; Item Num: K58214-001; Manufacturer: Coilcraft; Manufacturer Part Num: XEL4030-471MEC
L13 = INDUCTOR_IRON_ALT: IND 330nH SHLD 20% 25A 2.53mOHM; CLASS: DISCRETE; Item Num: K33012-001; Manufacturer: Coilcraft; Manufacturer Part Num: XAL6030-331MEC
R6814 = RESISTOR: RES 16.2K OHM 1% 1/16W 0402; AGILE_LINK: http://sj-agile9app/Agile/PLMServlet?action=OpenEmailObject&classid=10000&objid=146548997; Item Num: A93548-408; LIFECYCLE_PHASE: Active; Lead Free Status: Yes; MFR_LIFECYCLE: Active; Manufacturer: Yageo; Manufacturer Part Num: RC0402FR-0716K2L; Num Pins: 2; PART_SUBCLASS: RESISTORS; POWER: 1/16W; RoHS Compliant: Yes; TOLERANCE: 1%
R6832 = RESISTOR: RES 17.4K OHM 1% 1/16W 0402; AGILE_LINK: http://sj-agile9app/Agile/PLMServlet?action=OpenEmailObject&classid=10000&objid=146548997; Item Num: H30950-001; LIFECYCLE_PHASE: Active; Lead Free Status: Yes; MFR_LIFECYCLE: Active; Manufacturer: Panasonic; Manufacturer Part Num: ERJ-2RKF1742X; Num Pins: 2; PART_SUBCLASS: RESISTORS; POWER: 1/16W; RoHS Compliant: Yes; TOLERANCE: 1%
R6861 = RESISTOR: RES 536 OHM 1/16W 1% 0402 SMD; Item Num: A93548-009; Lead Free Status: Yes; Manufacturer: Yageo; Manufacturer Part Num: RC0402FR-07536RL; Num Pins: 2; Part Class: RESISTORS; Price: 0; RoHS Compliant: Yes; Tolerance: 1%
R6863 = RESISTOR: RES 28K OHM 1/16W 1% 0402 SMD; Item Num: A93548-249; Lead Free Status: Yes; Manufacturer: Yageo; Manufacturer Part Num: RC0402FR-0728KL; Num Pins: 2; Part Class: RESISTORS; Price: 0; RoHS Compliant: Yes; Tolerance: 1%
R6885 = RESISTOR: RES 698 OHM 1/16W 1% 0402 SMD; Item Num: A93548-389; Lead Free Status: Yes; Manufacturer: Yageo; Manufacturer Part Num: RC0402FR-07698RL; Num Pins: 2; Part Class: RESISTORS; Price: 0; RoHS Compliant: Yes; Tolerance: 1%
R666 R668 = RESISTOR: RES SMD 1K OHM 0.1% 1/16W 0402; Item Num: K21643-001; Lead Free Status: Yes; Manufacturer: Panasonic; Manufacturer Part Num: ERA-2AEB102X; Num Pins: 2; Part Class: Resistors; Power Rating: 1/16W; RoHS Compliant: Yes; TOLERANCE: 0.1%
BAT = BLANK_PART: BATTERY LITHIUM 3V COIN 16MM; Item Num: M62819-001; Manufacturer: Renata
BT1 = Battery_0: Battery Retainer Coin, 16.0mm 1 Cell SMD; Item Num: M62816-001; Manufacturer: Adam Tech; Manufacturer Part Num: BH-57A-5
D26 D27 = TVS_2: Diode Schottky 30 V 200mA (DC) Surface Mount SOT-23-3 (TO-236); Item Num: M62815-001; Manufacturer: ONSEMI; Manufacturer Part Num: BAT54LT1G
D28 = LT1389: Shunt Voltage Reference IC Fixed 1.25V V ±0.05% 20 mA 8-SO; Item Num: M62820-001; Manufacturer: ADI; Manufacturer Part Num: LT1389BCS8-1.25
R6903 = RESISTOR: RES SMD 243K OHM 1% 1/16W 0402; AGILE_LINK: http://sj-agile9app/Agile/PLMServlet?action=OpenEmailObject&classid=10000&objid=146548997; Item Num: M62814-001; LIFECYCLE_PHASE: Active; Lead Free Status: No; MFR_LIFECYCLE: Active; Manufacturer: Yageo; Manufacturer Part Num: AC0402FR-07243KL; Num Pins: 2; PART_SUBCLASS: RESISTORS; POWER: 1/16W; RoHS Compliant: Yes; TOLERANCE: 1%
R6905 = RESISTOR: RES ZERO OHM 1/16W 5% 0402 SMD; Item Num: A93549-001; Lead Free Status: No; Manufacturer: Yageo; Manufacturer Part Num: RC0402JR-070RL; Num Pins: 2; Part Class: RESISTORS; Price: 0; RoHS Compliant: Yes; Tolerance: 5%

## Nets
1V25_REF: D28.6(VOUT) R6903.2 R6905.1
3V3_STBY: C976.1 D26.1(Anode) R609.2 R641.2 R663.1 R664.2 R741.1 R1007.2 R6807.2 U80.9(VIN1) U80.10(VIN2) ; also on sheet 8 10 16 22 28 32 34 36 37 38 40 41 53 54 58
3VBAT: BT1.1(POS) D27.1(Anode)
12V_PCIE_IN: C1084.1 C1085.1 C1086.1 C1087.1 C1091.1 C1159.1 C1160.1 C1161.1 C1162.1 C1164.2 C1165.2 C1176.1 C1205.2 C1206.2 R1006.2 R6802.2 U93.B9(IN-) U93.B10(IN+) U93.G6(PVIN0) U93.G7(PVIN0) U93.G8(PVIN0) U93.G9(PVIN0) U93.G10(PVIN0) U93.H1(PVIN1) U93.H2(PVIN1) U93.H6(PVIN0) U93.H7(PVIN0) U93.J1(PVIN1) U93.J2(PVIN1) U93.J6(PVIN0) U93.J7(PVIN0) U93.K1(PVIN1) U93.K2(PVIN1) U93.K6(PVIN0) U93.k7(PVIN0_K7) U93.L1(PVIN1) U93.L2(PVIN1) U93.L6(PVIN0) U93.L7(PVIN0) U93.M1(PVIN1) U93.M2(PVIN1) U93.M6(PVIN0) U93.M7(PVIN0) U96.B9(IN-) U96.B10(IN+) U96.G6(PVIN0) U96.G7(PVIN0) U96.G8(PVIN0) U96.G9(PVIN0) U96.G10(PVIN0) U96.H1(PVIN1) U96.H2(PVIN1) U96.H6(PVIN0) U96.H7(PVIN0) U96.J1(PVIN1) U96.J2(PVIN1) U96.J6(PVIN0) U96.J7(PVIN0) U96.K1(PVIN1) U96.K2(PVIN1) U96.K6(PVIN0) U96.k7(PVIN0_K7) U96.L1(PVIN1) U96.L2(PVIN1) U96.L6(PVIN0) U96.L7(PVIN0) U96.M1(PVIN1) U96.M2(PVIN1) U96.M6(PVIN0) U96.M7(PVIN0) ; also on sheet 28 40 41 47 55 56
GND: BT1.2(NEG) C864.2 C866.1 C867.1 C868.1 C869.2 C976.2 C978.1 C979.1 C980.1 C981.2 C1084.2 C1085.2 C1086.2 C1087.2 C1091.2 C1092.2 C1127.1 C1128.1 C1129.1 C1132.1 C1133.1 C1134.1 C1135.1 C1136.2 C1138.1 C1139.1 C1142.1 C1143.1 C1144.1 C1145.1 C1146.2 C1154.2 C1157.1 C1159.2 C1160.2 C1161.2 C1162.2 C1164.1 C1165.1 C1166.1 C1167.1 C1170.1 C1171.1 C1172.1 C1173.1 C1174.2 C1176.2 C1181.1 C1182.1 C1185.1 C1186.1 C1187.1 C1188.1 C1189.2 C1205.1 C1206.1 C1208.2 C1216.2 D28.4(GND) D28.5(GND) J107.2(GND) R614.1 R668.2 R743.2 R6858.1 R6860.1 R6870.1 R6872.1 ST20.2 ST34.2 U70.5(GND) U70.11(EPAD) U80.5(GND) U80.11(EPAD) U93.D10(PGND) U93.G1(PGND) U93.G2(PGND) U93.G3(PGND) U93.G4(PGND) U93.G5(PGND) U93.H3(PGND) U93.H4(PGND) U93.H5(PGND) U93.H8(PGND) U93.H9(PGND) U93.H10(PGND) U93.J3(PGND) U93.J4(PGND) U93.J5(PGND) U93.J8(PGND) U93.J9(PGND) U93.J10(PGND) U93.K3(PGND) U93.K4(PGND) U93.K5(PGND) U93.K8(PGND) U93.K9(PGND) U93.K10(PGND) U93.L3(PGND) U93.L4(PGND) U93.L5(PGND) U93.L8(PGND) U93.L9(PGND) U93.L10(PGND) U93.M3(PGND) U93.M4(PGND) U93.M5(PGND) U93.M8(PGND) U93.M9(PGND) U93.M10(PGND) U96.D10(PGND) U96.G1(PGND) U96.G2(PGND) U96.G3(PGND) U96.G4(PGND) U96.G5(PGND) U96.H3(PGND) U96.H4(PGND) U96.H5(PGND) U96.H8(PGND) U96.H9(PGND) U96.H10(PGND) U96.J3(PGND) U96.J4(PGND) U96.J5(PGND) U96.J8(PGND) U96.J9(PGND) U96.J10(PGND) U96.K3(PGND) U96.K4(PGND) U96.K5(PGND) U96.K8(PGND) U96.K9(PGND) U96.K10(PGND) U96.L3(PGND) U96.L4(PGND) U96.L5(PGND) U96.L8(PGND) U96.L9(PGND) U96.L10(PGND) U96.M3(PGND) U96.M4(PGND) U96.M5(PGND) U96.M8(PGND) U96.M9(PGND) U96.M10(PGND) ; also on sheet 8 9 10 11 12 13 15 16 19 20 21 22 23 24 25 26 27 28 29 30 31 32 33 34 35 36 37 38 39 40 41 42 43 44 45 46 47 53 54 55 56 58
VCCBAT: R6904.1 R6905.2 ; also on sheet 23
ADI_ALERTn: R1007.1 R6807.1 U93.A2(ALERTN) U96.A2(ALERTN) ; also on sheet 10
EN_G1: R620.1 R637.1 ; also on sheet 10 42 43 44 45 46 47
EN_G2: R6808.1 ; also on sheet 10
EN_G3: R852.1 R6809.1 ; also on sheet 10 53
FPGA_VCC_HSSI_GXF_PG: R643.1 ; also on sheet 42
FPGA_VCC_PG: R642.1 ; also on sheet 42
FPGA_VCCERT_FGT_GXF: C1128.2 C1129.2 C1132.2 C1133.2 C1134.2 C1135.2 C1136.1 L10.2 R6852.2 R6857.2 ; also on sheet 23 39
FPGA_VCCERT_FGT_GXF_PG: R645.1 U93.C8(PGOOD0)
FPGA_VCCFUSEWR_GXF: C865.2 C866.2 C867.2 C868.2 R666.1 U70.1(VOUT1) U70.2(VOUT2) ; also on sheet 23 39
FPGA_VCCFUSEWR_GXF_PG: R663.2 R667.1 U70.4(POK)
FPGA_VCCH_PG: R644.1 R741.2 U80.4(POK)
FPGA_VCCH_SDM: C977.2 C978.2 C979.2 C980.2 R742.2 U80.1(VOUT1) U80.2(VOUT2) ; also on sheet 23 39
FPGA_VCCIO_1V2: C1181.2 C1182.2 C1185.2 C1186.2 C1187.2 C1188.2 C1189.1 L13.2 R6865.2 R6871.2 ; also on sheet 10 16 23 25 26 27 31 34 35 36 39 54 55 56
FPGA_VCCIO_1V2_PG: U96.F8(PGOOD1) ; also on sheet 53
FPGA_VCCIO_SDM_HPS: R6904.2 ; also on sheet 11 23 28 33 35 39 53
FPGA_VCCPT: C864.1 C1166.2 C1167.2 C1170.2 C1171.2 C1172.2 C1173.2 C1174.1 L12.2 R6862.2 R6869.2 U70.7(EN) U70.9(VIN1) U70.10(VIN2) ; also on sheet 23 28 39
FPGA_VCCPT_PG: R665.1 U96.C8(PGOOD0)
FPGA_VCCR_CORE: C1138.2 C1139.2 C1142.2 C1143.2 C1144.2 C1145.2 C1146.1 L11.2 R6855.2 R6859.2 ; also on sheet 23 39
FPGA_VCCR_CORE_PG: U93.F8(PGOOD1) ; also on sheet 53
LT_SCL: J107.3(SCL) R6882.2
LT_SDA: J107.1(SDA) R6881.2
MAX_I2C_SCL: R6882.1 U93.B3(SCL) U96.B3(SCL) ; also on sheet 8 10 32 33 34 37 40 42
MAX_I2C_SDA: R6881.1 U93.A3(SDA) U96.A3(SDA) ; also on sheet 8 10 32 33 34 37 40 42
PWRGD_G1: R641.1 R642.2 R643.2 R644.2 R645.2 ; also on sheet 10
PWRGD_G2: R664.1 R665.2 R667.2 ; also on sheet 10
U93_AGND: C1082.2 C1149.2 C1207.2 C1209.2 C1210.2 C1211.2 C1220.2 C1221.2 Q21.2(BASE) Q21.3(COLLECTOR) Q22.2(BASE) Q22.3(COLLECTOR) R857.2 R858.2 R1008.1 R6799.2 R6835.1 R6836.1 R6846.2 R6848.2 ST20.1 U93.C3(SGND) U93.C4(SGND) U93.C5(SGND) U93.C6(SGND) U93.C7(SGND) U93.D3(SGND) U93.D4(SGND) U93.D5(SGND) U93.D6(SGND) U93.D7(SGND) U93.E4(WP)
U93_VDD25: C1207.1 R6791.2 R6794.2 R6797.2 R6798.2 R6845.2 R6847.2 U93.F3(VDD25)
U93_VDD33: C1082.1 D22.1(C) R854.1 R855.1 R856.2 R6833.2 R6834.2 R6844.2 U93.F4(VDD33)
U96_AGND: C1156.2 C1178.2 C1179.2 C1191.2 C1193.2 C1217.2 C1222.2 C1223.2 Q23.2(BASE) Q23.3(COLLECTOR) Q24.2(BASE) Q24.3(COLLECTOR) R6819.1 R6821.2 R6822.2 R6829.1 R6831.1 R6832.1 R6874.2 R6876.2 ST34.1 U96.C3(SGND) U96.C4(SGND) U96.C5(SGND) U96.C6(SGND) U96.C7(SGND) U96.D3(SGND) U96.D4(SGND) U96.D5(SGND) U96.D6(SGND) U96.D7(SGND) U96.E4(WP)
U96_VDD25: C1217.1 R6812.2 R6813.2 R6814.2 R6815.2 R6873.2 R6875.2 U96.F3(VDD25)
U96_VDD33: C1156.1 D23.1(C) R6810.2 R6811.1 R6818.1 R6825.1 R6828.2 R6830.2 U96.F4(VDD33)
N5229121: C977.1 R742.1 R743.1 U80.3(VFB)
N5229137: C981.1 U80.6(SS)
N5229211: R609.1 R614.2 R620.2 U80.7(EN)
N6228318: R637.2 R6833.1 R6835.2 U93.C1(RUN0)
N6231213: C1081.2 L11.1 R6883.2 U93.F9(SW1) U93.N1(SW1) U93.N2(SW1) U93.N3(SW1) U93.N4(SW1) U93.N5(SW1) U93.P1(SW1) U93.P2(SW1) U93.P3(SW1) U93.P4(SW1) U93.P5(SW1)
N6231502: C1080.2 L10.1 R6853.2 U93.C10(SW0) U93.N6(SW0) U93.N7(SW0) U93.N8(SW0) U93.N9(SW0) U93.N10(SW0) U93.P6(SW0) U93.P7(SW0) U93.P8(SW0) U93.P9(SW0) U93.P10(SW0)
N6293185: R852.2 R6834.1 R6836.2 U93.C2(RUN1)
N6294472: R6844.1 U93.E3(SHARE_CLK)
N6295710: C1212.1 R6851.2 R6853.1 U93.B6(ISENSE0+)
N6295719: C1212.2 R6851.1 R6852.1 U93.A6(ISENSE0-)
N6295800: R6857.1 U93.A9(VSENSE0+)
N6296034: R854.2 U93.B1(FAULT1N)
N6296038: R855.2 U93.A1(FAULT0N)
N6296130: R6860.2 U93.E7(VSENSE1-)
N6296322: C1213.2 R6855.1 R6884.1 U93.B8(ISENSE1-)
N6296326: R6859.1 U93.F7(VSSENSE1+)
N6296367: C1213.1 R6883.1 R6884.2 U93.A8(ISENSE1+)
N6296487: R856.1 U93.A4(SYNC)
N6298711: C1092.1 D18.2 D19.2 U93.E10(INTVCC)
N6299162: C1208.1 U93.D9(EXTVCC)
N6302987: R858.1 R6794.1 U93.D1(ASEL0)
N6302998: R857.1 R6797.1 U93.E1(ASEL1)
N6372269: C1127.2 R1006.1 U93.D8(SVIN)
N6382900: C1149.1 U93.E6(ITHR1)
N6383007: C1211.1 U93.B7(ITHR0)
N6384083: C1210.1 U93.E5(ITH1)
N6384284: C1209.1 U93.A7(ITH0)
N6438706: R6858.2 U93.A10(VSENSE0-)
N6440564: C1220.1 Q21.1(EMITTER) U93.A5(TSNS0)
N6440883: C1221.1 Q22.1(EMITTER) U93.B5(TSNS1)
N6626632: R1008.2 R6798.1 U93.D2(VOUT0_CFG)
N6626636: R6791.1 R6799.1 U93.F1(VOUT1_CFG)
N6626640: R6845.1 R6846.1 U93.E2(FREQ_CFG)
N6626644: R6847.1 R6848.1 U93.F2(PHASE_CFG)
N6645972: C1154.1 D20.2 D21.2 U96.E10(INTVCC)
N6646134: C1157.2 R6802.1 U96.D8(SVIN)
N6646306: C1216.1 U96.D9(EXTVCC)
N6646832: C1158.1 D20.1(C) R6867.2
N6646840: C1158.2 L12.1 R6861.2 U96.C10(SW0) U96.N6(SW0) U96.N7(SW0) U96.N8(SW0) U96.N9(SW0) U96.N10(SW0) U96.P6(SW0) U96.P7(SW0) U96.P8(SW0) U96.P9(SW0) U96.P10(SW0)
N6647874: R6870.2 U96.A10(VSENSE0-)
N6648020: C1222.1 Q23.1(EMITTER) U96.A5(TSNS0)
N6648054: C1178.1 U96.A7(ITH0)
N6648084: C1179.1 U96.B7(ITHR0)
N6648272: R6808.2 R6830.1 R6831.2 U96.C1(RUN0)
N6648296: C1180.1 D21.1(C) R6868.2
N6648304: C1180.2 L13.1 R6885.2 U96.F9(SW1) U96.N1(SW1) U96.N2(SW1) U96.N3(SW1) U96.N4(SW1) U96.N5(SW1) U96.P1(SW1) U96.P2(SW1) U96.P3(SW1) U96.P4(SW1) U96.P5(SW1)
N6648338: R6809.2 R6828.1 R6829.2 U96.C2(RUN1)
N6648554: R6810.1 U96.A4(SYNC)
N6649026: R6811.2 U96.A1(FAULT0N)
N6649122: R6818.2 U96.B1(FAULT1N)
N6649146: R6812.1 R6819.2 U96.D1(ASEL0)
N6649150: R6813.1 R6821.1 U96.E1(ASEL1)
N6649154: R6814.1 R6832.2 U96.D2(VOUT0_CFG)
N6649158: R6815.1 R6822.1 U96.F1(VOUT1_CFG)
N6649162: R6873.1 R6874.1 U96.E2(FREQ_CFG)
N6649166: R6875.1 R6876.1 U96.F2(PHASE_CFG)
N6649352: R6872.2 U96.E7(VSENSE1-)
N6649458: R6825.2 U96.E3(SHARE_CLK)
N6649494: C1223.1 Q24.1(EMITTER) U96.B5(TSNS1)
N6649576: C1191.1 U96.E5(ITH1)
N6649610: C1193.1 U96.E6(ITHR1)
N6658100: C865.1 R666.2 R668.1 U70.3(VFB)
N6658116: C869.1 U70.6(SS)
N6923756: C1080.1 D18.1(C) R6849.2
N6924340: R6850.1 U93.F10(BOOST1)
N6924392: C1081.1 D19.1(C) R6850.2
N6992519: C1214.1 R6861.1 R6863.2 U96.B6(ISENSE0+)
N6992523: C1214.2 R6862.1 R6863.1 U96.A6(ISENSE0-)
N6993090: C1215.1 R6885.1 R6886.1 U96.A8(ISENSE1+)
N6993094: C1215.2 R6865.1 R6886.2 U96.B8(ISENSE1-)
N6995373: R6867.1 U96.C9(BOOST0)
N6996186: R6868.1 U96.F10(BOOST1)
N6998281: R6869.1 U96.A9(VSENSE0+)
N6999941: R6871.1 U96.F7(VSSENSE1+)
N7118059: D22.2 D23.2 J107.4(3.4V)
N8086837: D26.3(Cathode) D27.3(Cathode) R6903.1
N8383416: R6849.1 U93.C9(BOOST0)

Not connected (* = marked no-connect by the designer): D26 2(NC)*; D27 2(NC)*; D28 1(NC1)* 2(NC2)* 3(NC3)* 7(NC7)* 8(NC8)*; U70 8(NC)*; U80 8(NC)*; U93 B2(NC)* B4(NC)* E8(NC)* E9(NC)* F5(NC)* F6(NC)*; U96 B2(NC)* B4(NC)* E8(NC)* E9(NC)* F5(NC)* F6(NC)*

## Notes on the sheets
sheet 48
- Pullup on pg53
- VDOmax = 185mV
- 0.9V +/-3% @ 1.3mA
- VINabsmax = -0.3V to 6.5V
- Rup
- Vout = 0.5V x (Rup/Rdn + 1)
- Rdn
- ENth = 0.3V /0.8V / 1V
  ABSmax = 6.5V
sheet 49
- Input Isense
  not needed
- 1.0V +/-2.5%
- Remote sense at FPGA
- Place
  near
  L10
- Pull-ups on PG35
- 1.2V +/-5%
- Pull-up on pg57
- I2C ADDR = 74H
- VOUT0 = 1.05V by resistor,
  Override by NVM
- VOUT1 = 1.20V by resistor,
  Override by NVM
- FREQ = 500KHz by resistor,
  override by NVM
- PHASE = 0, 180
- Remote sense at FPGA
- Place
  near
  L11
- LTC Programming Header
- Pull-ups on PG35
- I2C ADDR = 74H
- I2C ACCESS HEADER
  Do not place on END of daisy chain
- AGND
- PGND
- PLACE Output decoupling caps
  close to the device.  Connect
  AGND and PGND at the point of
  cap GND connection.
sheet 50
- Input Isense
  not needed
- 1.8V +/-3%
- Remote sense at FPGA
- Place
  near
  L12
- Pull-ups on PG35
- 1.2V +/-5%
- I2C ADDR = 75H
- VOUT0 = 1.80V by resistor,
  Override by NVM
- VOUT1 = 1.20V by resistor,
  Override by NVM
- FREQ = 500KHz by resistor,
  override by NVM
- PHASE = 0, 180
- Remote sense at FPGA
- Place
  near
  L13
- I2C ADDR = 75H
- AGND
- PGND
- PLACE Output decoupling caps
  close to the device.  Connect
  AGND and PGND at the point of
  cap GND connection.
sheet 51
- Vout = 0.5V x (Rup/Rdn + 1)
- VDOmax = 185mV
- 1.0V +/-3% @ 200mA
- VINabsmax = -0.3V to 6.5V
- Rup
- Rdn
- ENth = 0.3V /0.8V / 1V
  ABSmax = 6.5V
sheet 52
- VCCBAT Circuit intended for FM76 Device with Crypto Support
- (1V - 1.8V)
- ~6.4uA
- (1.8V)
- 0.8uA
- (Default)
- Share pad so only
  one Resistor can be
  installed at a time
